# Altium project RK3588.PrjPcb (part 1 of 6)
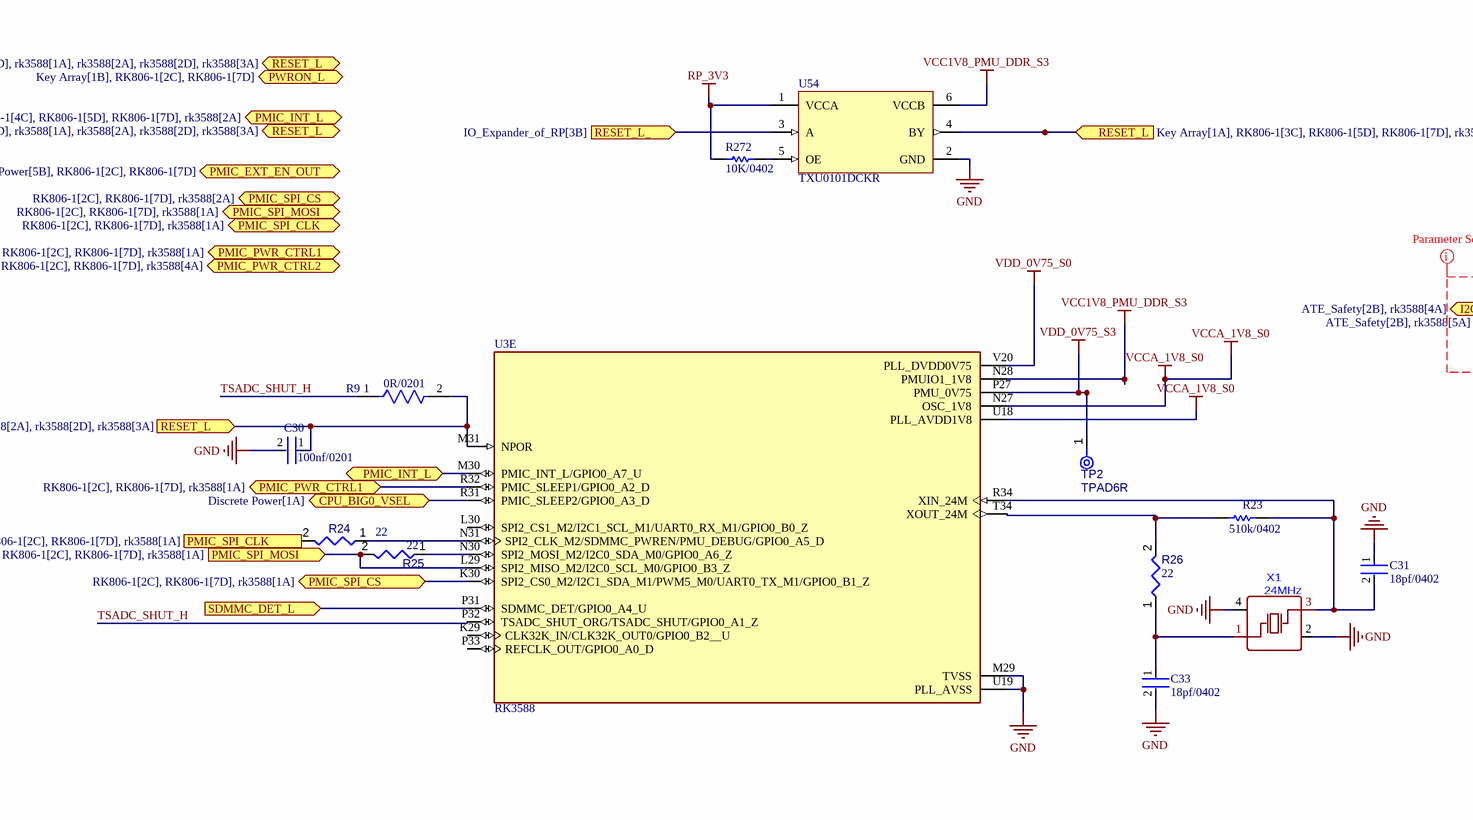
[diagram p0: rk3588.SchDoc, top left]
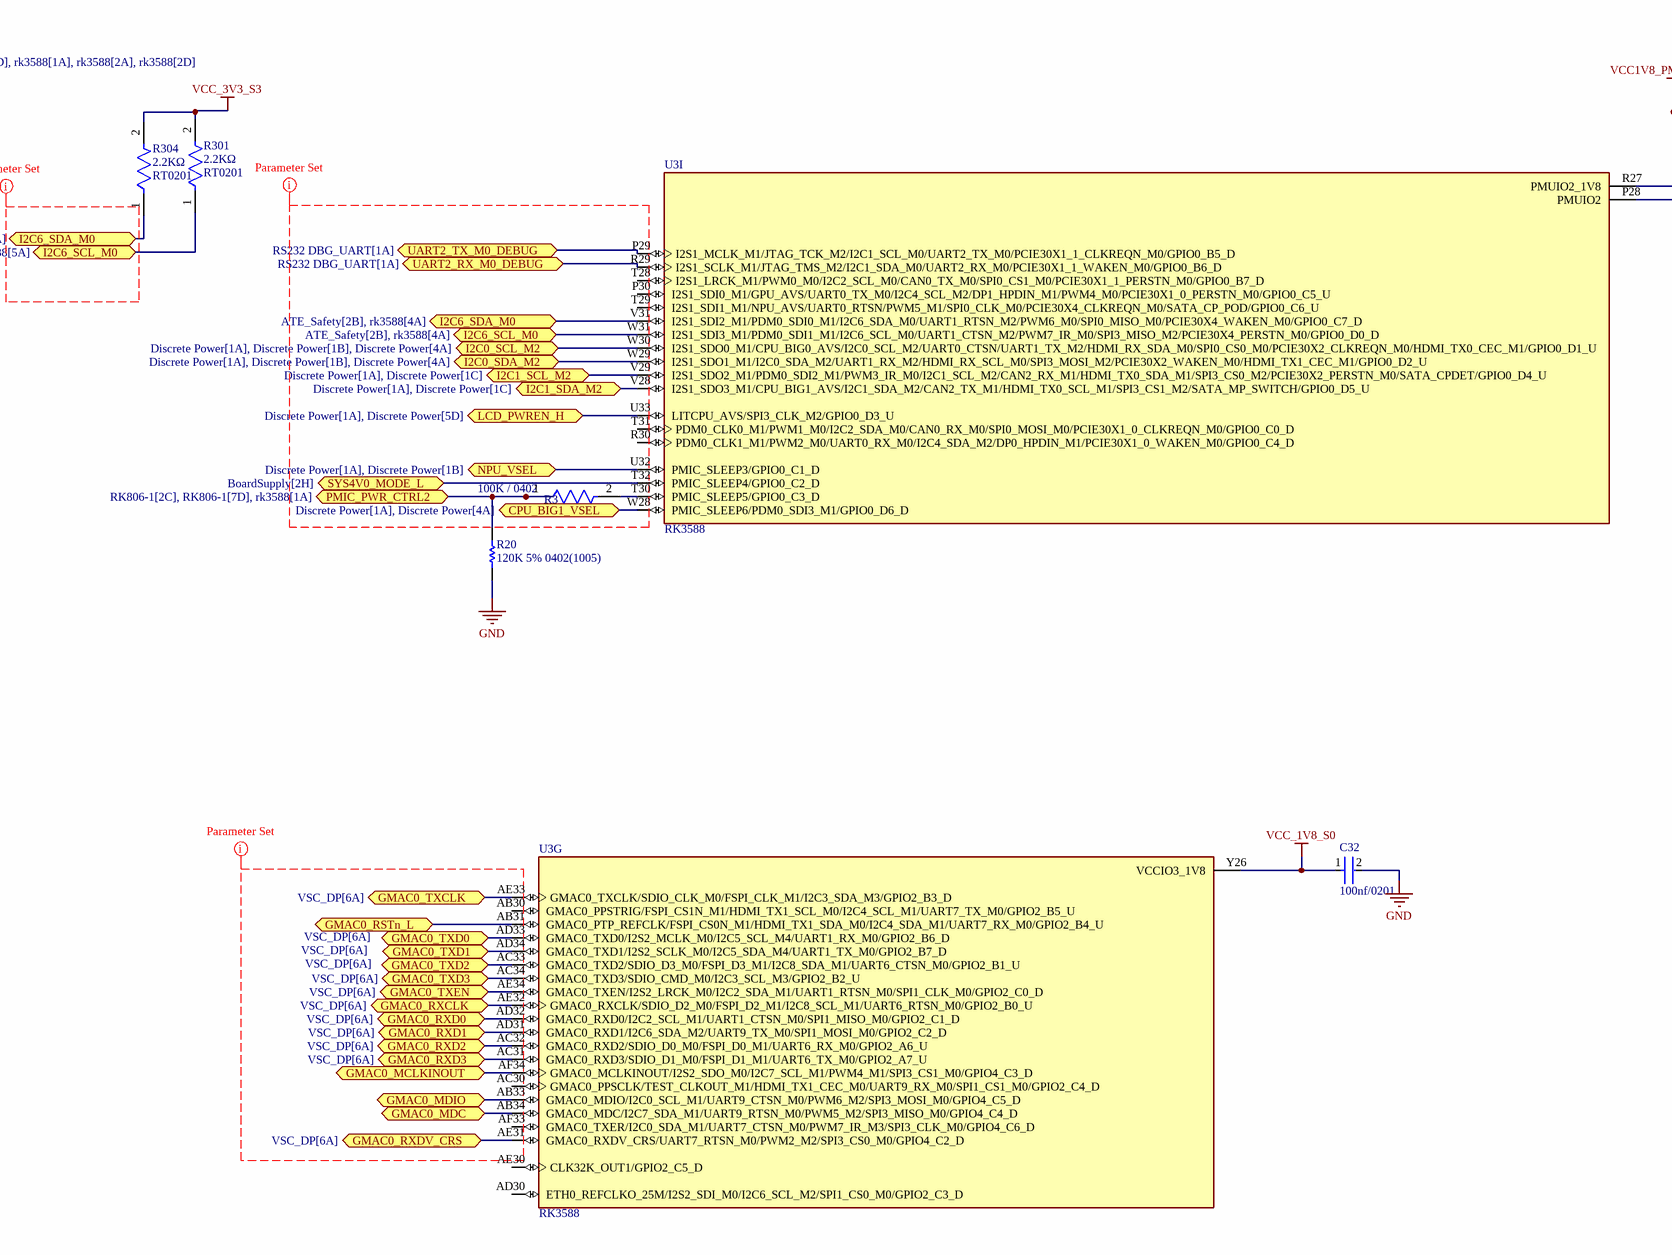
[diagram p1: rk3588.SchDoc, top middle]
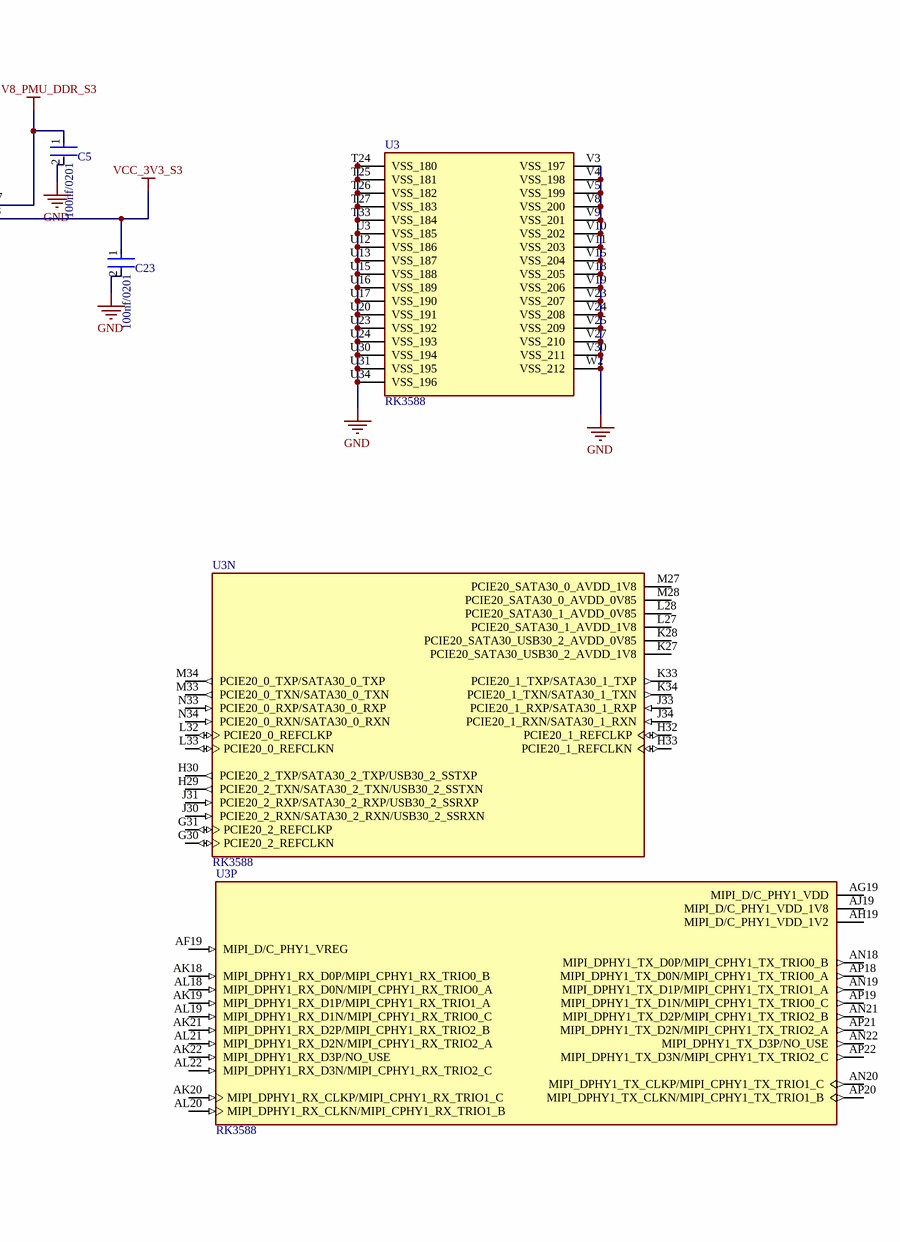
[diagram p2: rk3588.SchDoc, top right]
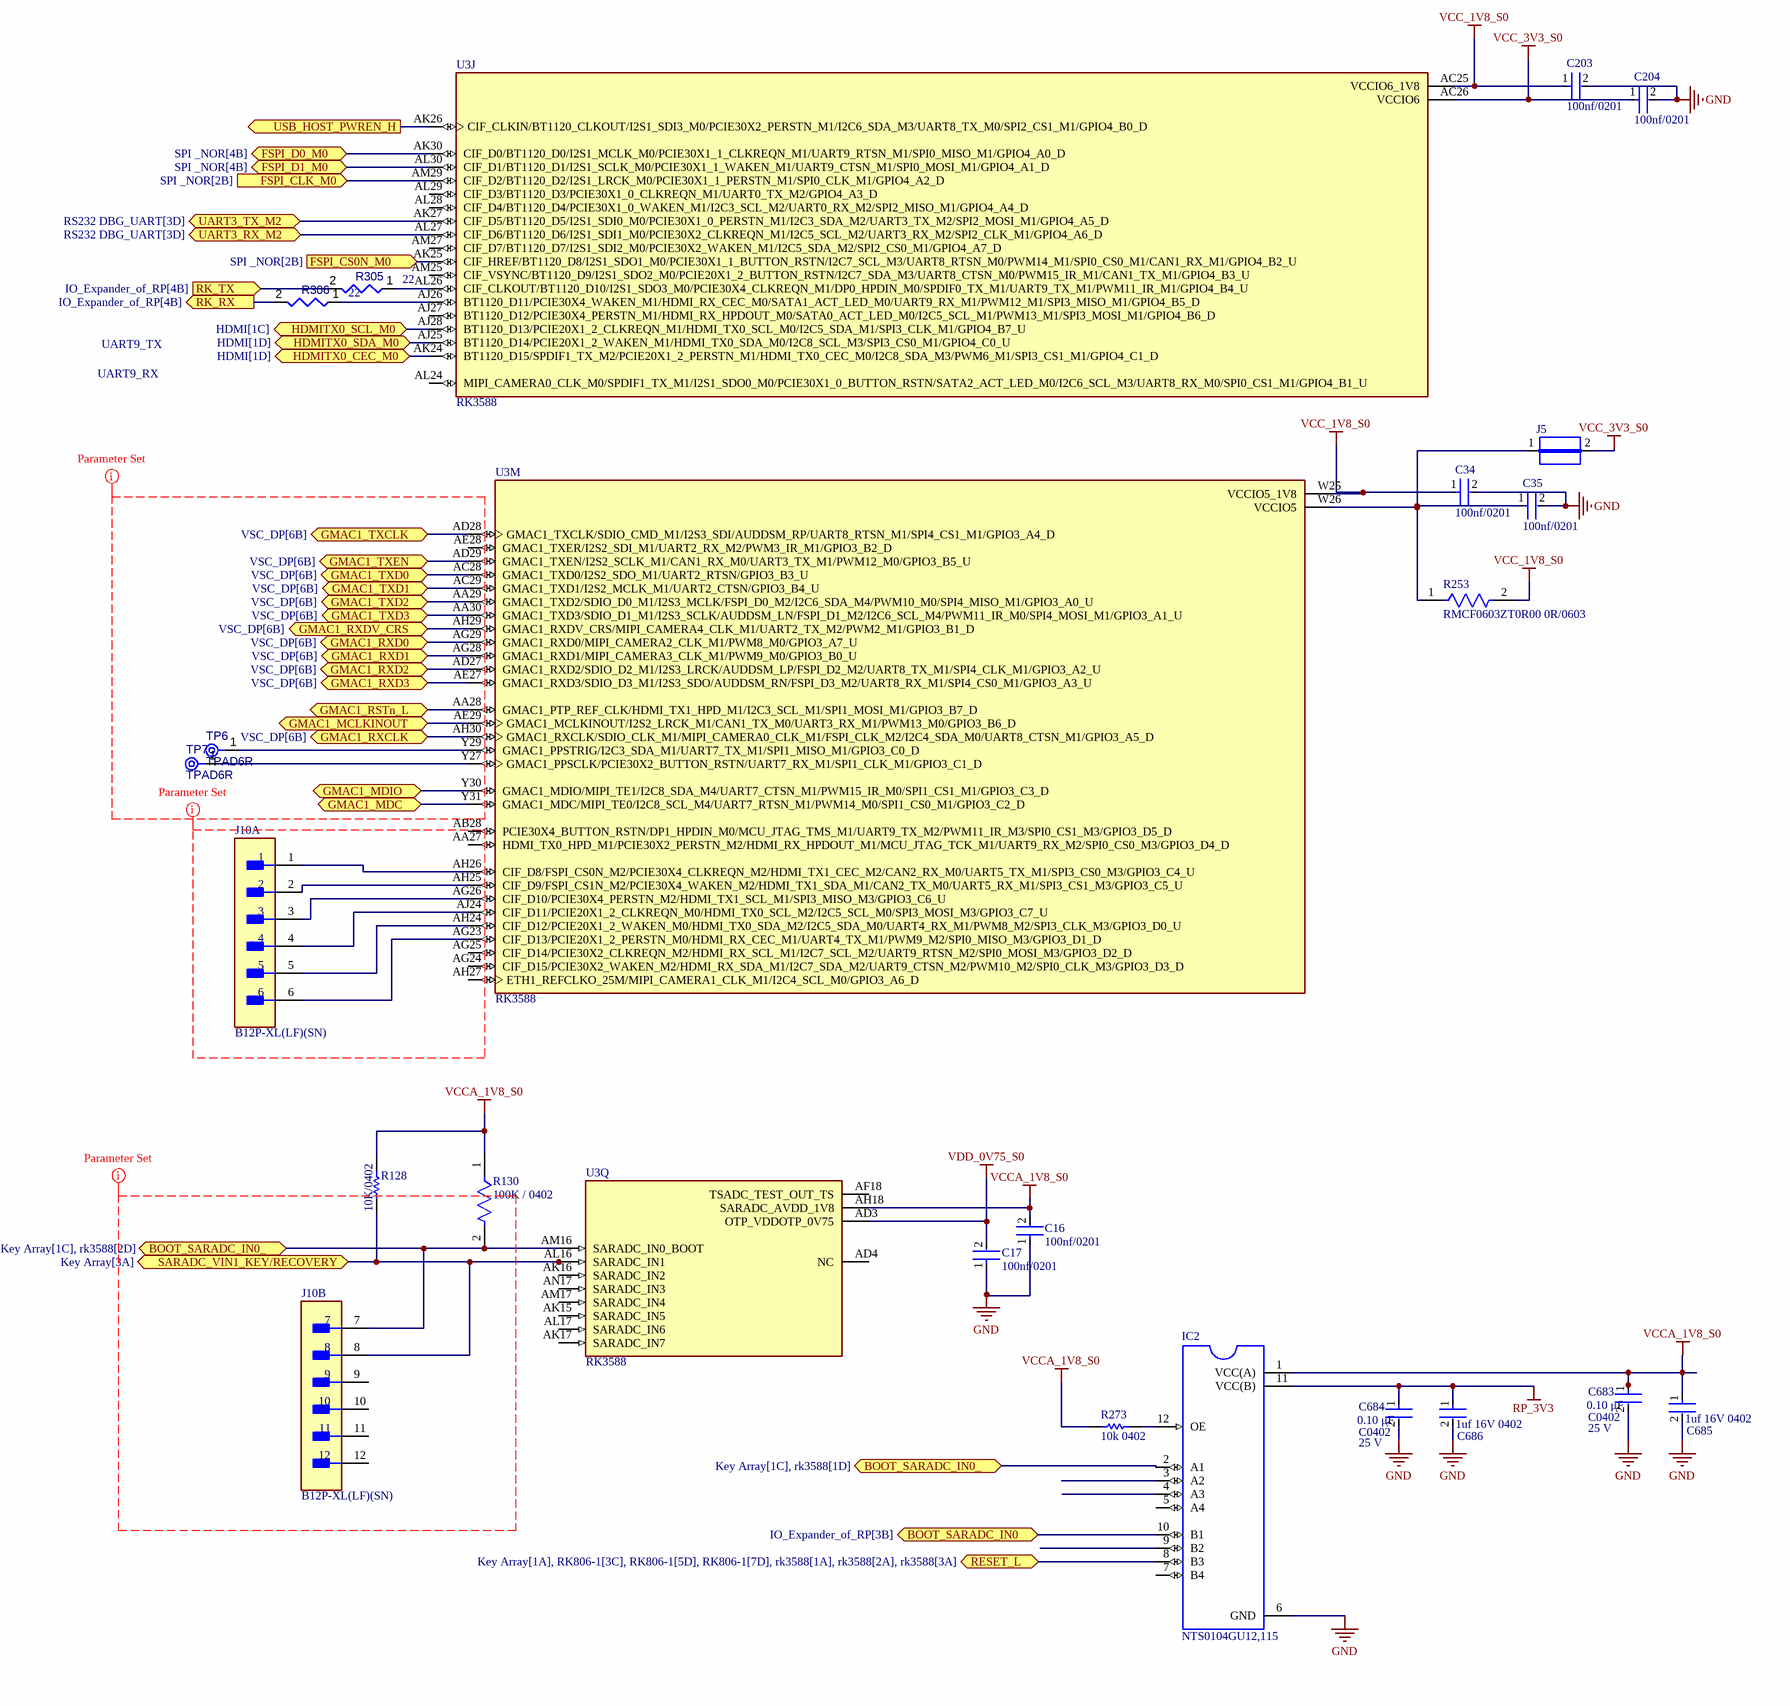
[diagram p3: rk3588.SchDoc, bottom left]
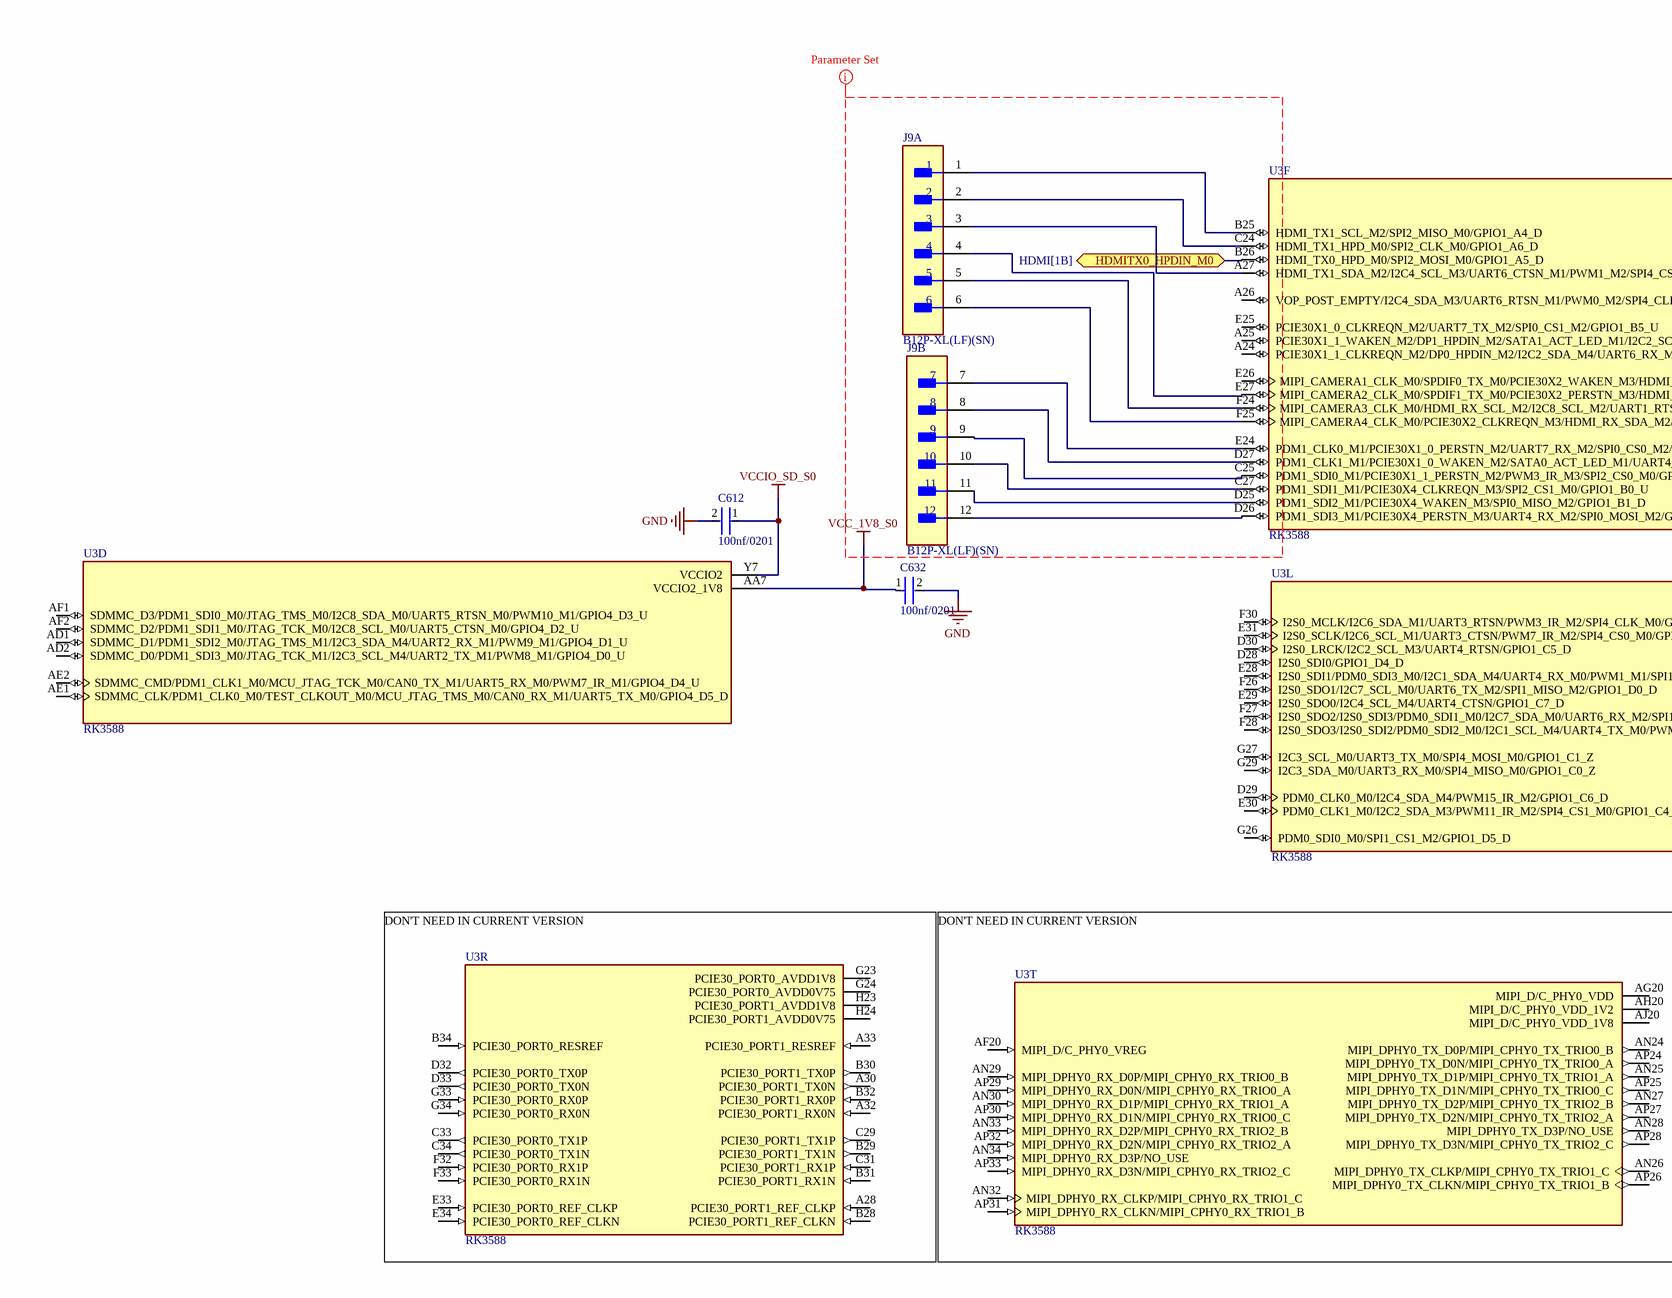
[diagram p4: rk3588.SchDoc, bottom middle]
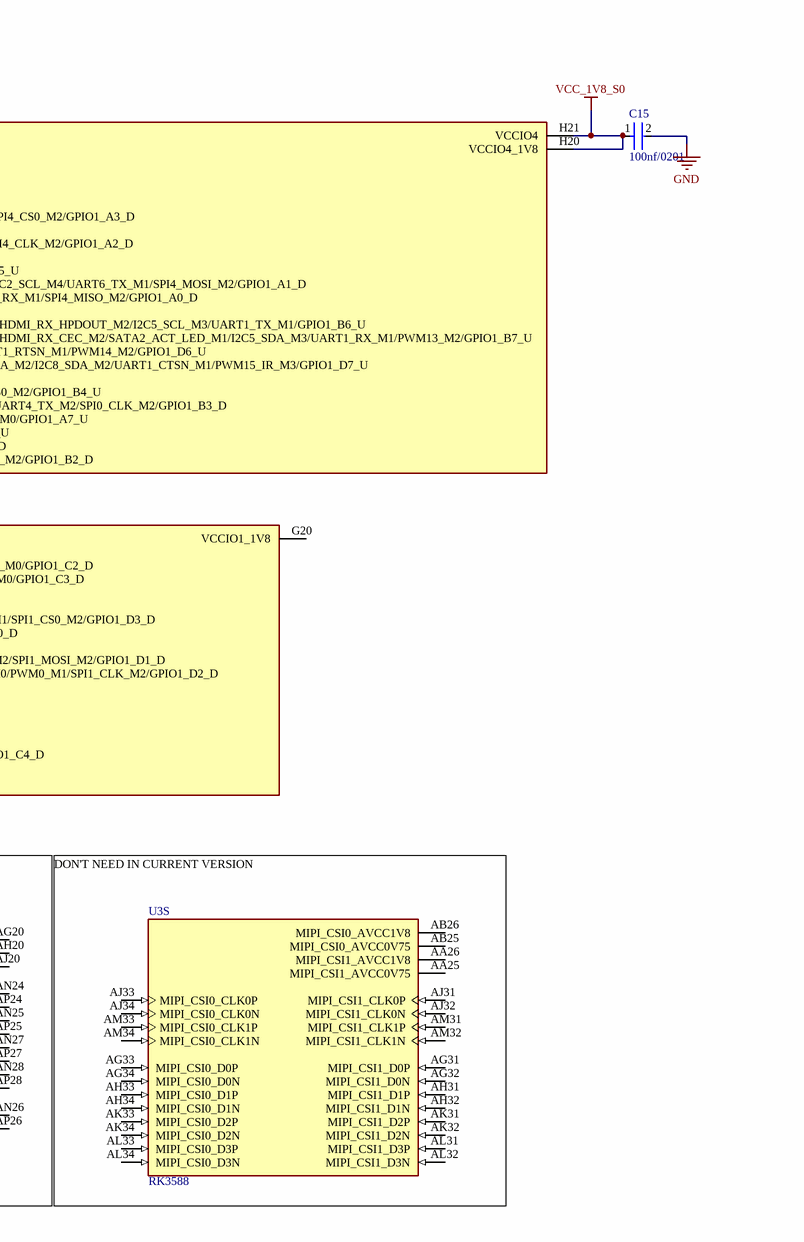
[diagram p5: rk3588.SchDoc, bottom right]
22 sheets, 1254 parts. Net scope: flat (ports and power ports of the same name join across sheets).
Board files: PCB1.PcbDoc, rk860_fp.pcbdoc
Sheets:
  rk3588.SchDoc
  RK3588_Power.SchDoc
  rk3588_LPDDR4.SchDoc
  RK806-1.SchDoc
  ATE_Safety.SchDoc
  SPI _NOR.SchDoc
  LAN9696.SchDoc
  LAN9696_Supply.SchDoc
  LAN_Supply.SchDoc
  8841.SchDoc
  EMMC.SchDoc
  LPDDR4_EDA.SchDoc
  BoardSupply.SchDoc
  RK3588_USB2.0_USB3.0.SchDoc
  HDMI.SchDoc
  Discrete Power.SchDoc
  RS232 DBG_UART.SchDoc
  Key Array.SchDoc
  RP2350.SchDoc
  IO_Expander_of_RP.SchDoc
  VSC_DP.SchDoc
  Level_Shifter.SchDoc

## Sheet rk3588.SchDoc
size D; SheetNumber: 1; SheetTotal: 22

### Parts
C5  100nf/0201  [FP-CL03-IPC_C]
C15  100nf/0201  [FP-CL03-IPC_C]
C16  100nf/0201  [FP-CL03-IPC_C]
C17  100nf/0201  [FP-CL03-IPC_C]
C23  100nf/0201  [FP-CL03-IPC_C]
C30  100nf/0201  [FP-CL03-IPC_C]
C31  18pf/0402  [FP-C0402-BB-MFG]
C32  100nf/0201  [FP-CL03-IPC_C]
C33  18pf/0402  [FP-C0402-BB-MFG]
C34  100nf/0201  [FP-CL03-IPC_C]
C35  100nf/0201  [FP-CL03-IPC_C]
C203  100nf/0201  [FP-CL03-IPC_C]
C204  100nf/0201  [FP-CL03-IPC_C]
C612  100nf/0201  [FP-CL03-IPC_C]
C632  100nf/0201  [FP-CL03-IPC_C]
C683  value 0.10 μF  Package: C0402  Voltage Rating: 25 V  [FP-C0402-BB-MFG]  (hidden comment: C0402C104M3PAC7867)
C684  value 0.10 μF  Package: C0402  Voltage Rating: 25 V  [FP-C0402-BB-MFG]  (hidden comment: C0402C104M3PAC7867)
C685  1uf 16V 0402  [FP-CC0402-MFG]
C686  1uf 16V 0402  [FP-CC0402-MFG]
IC2  NTS0104GU12,115  [QFN40P170X200X50-12N]
J5  JUMPER  [JUMPER]  (value not drawn)
J9  B12P-XL(LF)(SN)  [FP-B12P-XL_LF_SN-MFG]  (parts A,B of 2)
J10  B12P-XL(LF)(SN)  [FP-B12P-XL_LF_SN-MFG]  (parts A,B of 2)
R3  100K / 0402  [FP-CRGP0402-IPC_C]
R9  0R/0201  [FP-RMCF0201-IPC_C]
R20  120K 5% 0402(1005)  [RESC0402(1005)_M]
R23  510k/0402  [RESC1005X40X25NL05T10]
R24  value 22  [RESC0402(1005)_L]  (hidden comment: 22R2J)
R25  value 22  [RESC0402(1005)_L]  (hidden comment: 22R2J)
R26  value 22  [RESC0402(1005)_L]  (hidden comment: 22R2J)
R128  10K/0402  [RESC1005X40X20NL05T10]
R130  100K / 0402  [FP-CRGP0402-IPC_C]
R253  RMCF0603ZT0R00 0R/0603  [FP-RMCF0603-MFG]
R272  10K/0402  [RESC1005X40X20NL05T10]
R273  10k 0402  [RESC1005X40X20NL05T10]
R301  Resistance: 2.2KΩ  Package: RT0201  [FP-RT0201-MFG]  (hidden comment: RT0201FRE072K2L)
R304  Resistance: 2.2KΩ  Package: RT0201  [FP-RT0201-MFG]  (hidden comment: RT0201FRE072K2L)
R305  value 22  [RESC0402(1005)_L]  (hidden comment: 22R2J)
R306  value 22  [RESC0402(1005)_L]  (hidden comment: 22R2J)
TP2  TPAD6R  [TP06R]  (no BOM)
TP6  TPAD6R  [TP06R]  (no BOM)
TP7  TPAD6R  [TP06R]  (no BOM)
U3  RK3588  [BGA1088C65P34X34_2300X2300X204N]  (parts D,E,F,G,I,J,L,M,N,P,Q,R,S,T,27 of 30)
U54  TXU0101DCKR  [FP-DCK0006A-MFG]
X1  24MHz  [CRYSTAL-SMD_4P-L3.2-W2.5-BL]

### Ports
BOOT_SARADC_IN0 (bidir, see IO_Expander_of_RP[3B]), BOOT_SARADC_IN0_ (bidir, see Key Array[1C], rk3588[1D]), BOOT_SARADC_IN0_ (bidir, see Key Array[1C], rk3588[2D]), CPU_BIG0_VSEL (bidir, see Discrete Power[1A]), CPU_BIG1_VSEL (bidir, see Discrete Power[1A], Discrete Power[4A]), FSPI_CLK_M0 (in, see SPI _NOR[2B]), FSPI_CS0N_M0 (in, see SPI _NOR[2B]), FSPI_D0_M0 (bidir, see SPI _NOR[4B]), FSPI_D1_M0 (bidir, see SPI _NOR[4B]), GMAC0_MCLKINOUT (bidir), GMAC0_MDC (bidir), GMAC0_MDIO (bidir), GMAC0_RSTn_L (bidir), GMAC0_RXCLK (bidir, see VSC_DP[6A]), GMAC0_RXD0 (bidir, see VSC_DP[6A]), GMAC0_RXD1 (bidir, see VSC_DP[6A]), GMAC0_RXD2 (bidir, see VSC_DP[6A]), GMAC0_RXD3 (bidir, see VSC_DP[6A]), GMAC0_RXDV_CRS (bidir, see VSC_DP[6A]), GMAC0_TXCLK (bidir, see VSC_DP[6A]), GMAC0_TXD0 (bidir, see VSC_DP[6A]), GMAC0_TXD1 (bidir, see VSC_DP[6A]), GMAC0_TXD2 (bidir, see VSC_DP[6A]), GMAC0_TXD3 (bidir, see VSC_DP[6A]), GMAC0_TXEN (bidir, see VSC_DP[6A]), GMAC1_MCLKINOUT (bidir), GMAC1_MDC (bidir), GMAC1_MDIO (bidir), GMAC1_RSTn_L (bidir), GMAC1_RXCLK (bidir, see VSC_DP[6B]), GMAC1_RXD0 (bidir, see VSC_DP[6B]), GMAC1_RXD1 (bidir, see VSC_DP[6B]), GMAC1_RXD2 (bidir, see VSC_DP[6B]), GMAC1_RXD3 (bidir, see VSC_DP[6B]), GMAC1_RXDV_CRS (bidir, see VSC_DP[6B]), GMAC1_TXCLK (bidir, see VSC_DP[6B]), GMAC1_TXD0 (bidir, see VSC_DP[6B]), GMAC1_TXD1 (bidir, see VSC_DP[6B]), GMAC1_TXD2 (bidir, see VSC_DP[6B]), GMAC1_TXD3 (bidir, see VSC_DP[6B]), GMAC1_TXEN (bidir, see VSC_DP[6B]), HDMITX0_CEC_M0 (bidir, see HDMI[1D]), HDMITX0_HPDIN_M0 (bidir, see HDMI[1B]), HDMITX0_SCL_M0 (bidir, see HDMI[1C]), HDMITX0_SDA_M0 (bidir, see HDMI[1D]), I2C0_SCL_M2 (bidir, see Discrete Power[1A], Discrete Power[1B], Discrete Power[4A]), I2C0_SDA_M2 (bidir, see Discrete Power[1A], Discrete Power[1B], Discrete Power[4A]), I2C1_SCL_M2 (bidir, see Discrete Power[1A], Discrete Power[1C]), I2C1_SDA_M2 (bidir, see Discrete Power[1A], Discrete Power[1C]), I2C6_SCL_M0 (bidir, see ATE_Safety[2B], rk3588[4A]), I2C6_SCL_M0 (bidir, see ATE_Safety[2B], rk3588[5A]), I2C6_SDA_M0 (bidir, see ATE_Safety[2B], rk3588[4A]), LCD_PWREN_H (bidir, see Discrete Power[1A], Discrete Power[5D]), NPU_VSEL (bidir, see Discrete Power[1A], Discrete Power[1B]), PMIC_EXT_EN_OUT (bidir, see Discrete Power[5B], RK806-1[2C], RK806-1[7D]), PMIC_INT_L (bidir, see RK806-1[4C], RK806-1[5D], RK806-1[7D], rk3588[1A]), PMIC_INT_L (bidir, see RK806-1[4C], RK806-1[5D], RK806-1[7D], rk3588[2A]), PMIC_PWR_CTRL1 (bidir, see RK806-1[2C], RK806-1[7D], rk3588[1A]), PMIC_PWR_CTRL2 (bidir, see RK806-1[2C], RK806-1[7D], rk3588[1A]), PMIC_PWR_CTRL2 (bidir, see RK806-1[2C], RK806-1[7D], rk3588[4A]), PMIC_SPI_CLK (bidir, see RK806-1[2C], RK806-1[7D], rk3588[1A]), PMIC_SPI_CLK (in, see RK806-1[2C], RK806-1[7D], rk3588[1A]), PMIC_SPI_CS (bidir, see RK806-1[2C], RK806-1[7D], rk3588[1A]), PMIC_SPI_CS (bidir, see RK806-1[2C], RK806-1[7D], rk3588[2A]), PMIC_SPI_MOSI (bidir, see RK806-1[2C], RK806-1[7D], rk3588[1A]), PMIC_SPI_MOSI (in, see RK806-1[2C], RK806-1[7D], rk3588[1A]), PWRON_L (bidir, see Key Array[1B], RK806-1[2C], RK806-1[7D]), RESET_L (bidir, see Key Array[1A], RK806-1[3C], RK806-1[5D], RK806-1[7D], rk3588[1A], rk3588[2A], rk3588[2D], rk3588[3A]), RESET_L (bidir, see Key Array[1A], RK806-1[3C], RK806-1[5D], RK806-1[7D], rk3588[1A], rk3588[2A], rk3588[3A]), RESET_L (in, see Key Array[1A], RK806-1[3C], RK806-1[5D], RK806-1[7D], rk3588[1A], rk3588[2A], rk3588[2D]), RESET_L (in, see Key Array[1A], RK806-1[3C], RK806-1[5D], RK806-1[7D], rk3588[2A], rk3588[2D], rk3588[3A]), RESET_L_ (in, see IO_Expander_of_RP[3B]), RK_RX (out, see IO_Expander_of_RP[4B]), RK_TX (in, see IO_Expander_of_RP[4B]), SARADC_VIN1_KEY/RECOVERY (bidir, see Key Array[3A]), SDMMC_DET_L (in), SYS4V0_MODE_L (bidir, see BoardSupply[2H]), UART2_RX_M0_DEBUG (bidir, see RS232 DBG_UART[1A]), UART2_TX_M0_DEBUG (bidir, see RS232 DBG_UART[1A]), UART3_RX_M2 (bidir, see RS232 DBG_UART[3D]), UART3_TX_M2 (bidir, see RS232 DBG_UART[3D]), USB_HOST_PWREN_H (out)

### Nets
GND: C5.2 C15.2 C16.1 C17.1 C23.2 C30.2 C31.1 C32.2 C33.2 C34.2 C35.2 C203.2 C204.2 C612.2 C632.2 C683.2 C684.2 C685.2 C686.2 IC2.6(GND) R20.1 U3.M29(TVSS) U3.T24(VSS_180) U3.T25(VSS_181) U3.T26(VSS_182) U3.T27(VSS_183) U3.T33(VSS_184) U3.U3(VSS_185) U3.U12(VSS_186) U3.U13(VSS_187) U3.U15(VSS_188) U3.U16(VSS_189) U3.U17(VSS_190) U3.U19(PLL_AVSS) U3.U20(VSS_191) U3.U23(VSS_192) U3.U24(VSS_193) U3.U30(VSS_194) U3.U31(VSS_195) U3.U34(VSS_196) U3.V3(VSS_197) U3.V4(VSS_198) U3.V5(VSS_199) U3.V8(VSS_200) U3.V9(VSS_201) U3.V10(VSS_202) U3.V11(VSS_203) U3.V15(VSS_204) U3.V18(VSS_205) U3.V19(VSS_206) U3.V23(VSS_207) U3.V24(VSS_208) U3.V25(VSS_209) U3.V27(VSS_210) U3.V30(VSS_211) U3.W2(VSS_212) U54.2(GND) X1.2(GND) X1.4(GND)
RP_3V3: C684.1 C686.1 IC2.11(VCC(B)) R272.2 U54.1(VCCA)  [project net 3V3]
VCC1V8_PMU_DDR_S3: C5.1 U3.N28(PMUIO1_1V8) U3.R27(PMUIO2_1V8) U54.6(VCCB)
VCC_1V8_S0: C15.1 C32.1 C34.1 C203.1 C632.1 R253.2 U3.AA7(VCCIO2_1V8) U3.AC25(VCCIO6_1V8) U3.H20(VCCIO4_1V8) U3.H21(VCCIO4) U3.W25(VCCIO5_1V8) U3.Y26(VCCIO3_1V8)
VCC_3V3_S0: C204.1 J5.2 U3.AC26(VCCIO6)
VCC_3V3_S3: C23.1 R301.2 R304.2 U3.P28(PMUIO2)  [project net EMMC_VCC]
VCCA_1V8_S0: C16.2 C683.1 C685.1 IC2.1(VCC(A)) R128.2 R130.1 R273.1 U3.AH18(SARADC_AVDD_1V8) U3.N27(OSC_1V8) U3.U18(PLL_AVDD1V8)  [project net VCCA_1V8]
VCCIO_SD_S0: C612.1 U3.Y7(VCCIO2)  [project net PLDO5]
VDD_0V75_S0: C17.2 U3.AD3(OTP_VDDOTP_0V75) U3.V20(PLL_DVDD0V75)  [project net NLDO5]
VDD_0V75_S3: TP2.1(TP) U3.P27(PMU_0V75)  [project net NLDO1]
BOOT_SARADC_IN0: IC2.10(B1) ; port BOOT_SARADC_IN0
BOOT_SARADC_IN0_: IC2.2(A1) J10.7 R130.2 U3.AM16(SARADC_IN0_BOOT) ; port BOOT_SARADC_IN0_
CPU_BIG0_VSEL: U3.R31(PMIC_SLEEP2/GPIO0_A3_D) ; port CPU_BIG0_VSEL
CPU_BIG1_VSEL: U3.W28(PMIC_SLEEP6/PDM0_SDI3_M1/GPIO0_D6_D) ; port CPU_BIG1_VSEL
FSPI_CLK_M0: U3.AM29(CIF_D2/BT1120_D2/I2S1_LRCK_M0/PCIE30X1_1_PERSTN_M1/SPI0_CLK_M1/GPIO4_A2_D) ; port FSPI_CLK_M0
FSPI_CS0N_M0: U3.AK25(CIF_HREF/BT1120_D8/I2S1_SDO1_M0/PCIE30X1_1_BUTTON_RSTN/I2C7_SCL_M3/UART8_RTSN_M0/PWM14_M1/SPI0_CS0_M1/CAN1_RX_M1/GPIO4_B2_U) ; port FSPI_CS0N_M0
FSPI_D0_M0: U3.AK30(CIF_D0/BT1120_D0/I2S1_MCLK_M0/PCIE30X1_1_CLKREQN_M1/UART9_RTSN_M1/SPI0_MISO_M1/GPIO4_A0_D) ; port FSPI_D0_M0
FSPI_D1_M0: U3.AL30(CIF_D1/BT1120_D1/I2S1_SCLK_M0/PCIE30X1_1_WAKEN_M1/UART9_CTSN_M1/SPI0_MOSI_M1/GPIO4_A1_D) ; port FSPI_D1_M0
GMAC0_MCLKINOUT: U3.AF34(GMAC0_MCLKINOUT/I2S2_SDO_M0/I2C7_SCL_M1/PWM4_M1/SPI3_CS1_M0/GPIO4_C3_D) ; port GMAC0_MCLKINOUT
GMAC0_MDC: U3.AB34(GMAC0_MDC/I2C7_SDA_M1/UART9_RTSN_M0/PWM5_M2/SPI3_MISO_M0/GPIO4_C4_D) ; port GMAC0_MDC
GMAC0_MDIO: U3.AB33(GMAC0_MDIO/I2C0_SCL_M1/UART9_CTSN_M0/PWM6_M2/SPI3_MOSI_M0/GPIO4_C5_D) ; port GMAC0_MDIO
GMAC0_RSTn_L: U3.AB31(GMAC0_PTP_REFCLK/FSPI_CS0N_M1/HDMI_TX1_SDA_M0/I2C4_SDA_M1/UART7_RX_M0/GPIO2_B4_U) ; port GMAC0_RSTn_L
GMAC0_RXCLK: U3.AE32(GMAC0_RXCLK/SDIO_D2_M0/FSPI_D2_M1/I2C8_SCL_M1/UART6_RTSN_M0/GPIO2_B0_U) ; port GMAC0_RXCLK
GMAC0_RXD0: U3.AD32(GMAC0_RXD0/I2C2_SCL_M1/UART1_CTSN_M0/SPI1_MISO_M0/GPIO2_C1_D) ; port GMAC0_RXD0
GMAC0_RXD1: U3.AD31(GMAC0_RXD1/I2C6_SDA_M2/UART9_TX_M0/SPI1_MOSI_M0/GPIO2_C2_D) ; port GMAC0_RXD1
GMAC0_RXD2: U3.AC32(GMAC0_RXD2/SDIO_D0_M0/FSPI_D0_M1/UART6_RX_M0/GPIO2_A6_U) ; port GMAC0_RXD2
GMAC0_RXD3: U3.AC31(GMAC0_RXD3/SDIO_D1_M0/FSPI_D1_M1/UART6_TX_M0/GPIO2_A7_U) ; port GMAC0_RXD3
GMAC0_RXDV_CRS: U3.AE31(GMAC0_RXDV_CRS/UART7_RTSN_M0/PWM2_M2/SPI3_CS0_M0/GPIO4_C2_D) ; port GMAC0_RXDV_CRS
GMAC0_TXCLK: U3.AE33(GMAC0_TXCLK/SDIO_CLK_M0/FSPI_CLK_M1/I2C3_SDA_M3/GPIO2_B3_D) ; port GMAC0_TXCLK
GMAC0_TXD0: U3.AD33(GMAC0_TXD0/I2S2_MCLK_M0/I2C5_SCL_M4/UART1_RX_M0/GPIO2_B6_D) ; port GMAC0_TXD0
GMAC0_TXD1: U3.AD34(GMAC0_TXD1/I2S2_SCLK_M0/I2C5_SDA_M4/UART1_TX_M0/GPIO2_B7_D) ; port GMAC0_TXD1
GMAC0_TXD2: U3.AC33(GMAC0_TXD2/SDIO_D3_M0/FSPI_D3_M1/I2C8_SDA_M1/UART6_CTSN_M0/GPIO2_B1_U) ; port GMAC0_TXD2
GMAC0_TXD3: U3.AC34(GMAC0_TXD3/SDIO_CMD_M0/I2C3_SCL_M3/GPIO2_B2_U) ; port GMAC0_TXD3
GMAC0_TXEN: U3.AE34(GMAC0_TXEN/I2S2_LRCK_M0/I2C2_SDA_M1/UART1_RTSN_M0/SPI1_CLK_M0/GPIO2_C0_D) ; port GMAC0_TXEN
GMAC1_MCLKINOUT: U3.AE29(GMAC1_MCLKINOUT/I2S2_LRCK_M1/CAN1_TX_M0/UART3_RX_M1/PWM13_M0/GPIO3_B6_D) ; port GMAC1_MCLKINOUT
GMAC1_MDC: U3.Y31(GMAC1_MDC/MIPI_TE0/I2C8_SCL_M4/UART7_RTSN_M1/PWM14_M0/SPI1_CS0_M1/GPIO3_C2_D) ; port GMAC1_MDC
GMAC1_MDIO: U3.Y30(GMAC1_MDIO/MIPI_TE1/I2C8_SDA_M4/UART7_CTSN_M1/PWM15_IR_M0/SPI1_CS1_M1/GPIO3_C3_D) ; port GMAC1_MDIO
GMAC1_RSTn_L: U3.AA28(GMAC1_PTP_REF_CLK/HDMI_TX1_HPD_M1/I2C3_SCL_M1/SPI1_MOSI_M1/GPIO3_B7_D) ; port GMAC1_RSTn_L
GMAC1_RXCLK: U3.AH30(GMAC1_RXCLK/SDIO_CLK_M1/MIPI_CAMERA0_CLK_M1/FSPI_CLK_M2/I2C4_SDA_M0/UART8_CTSN_M1/GPIO3_A5_D) ; port GMAC1_RXCLK
GMAC1_RXD0: U3.AG29(GMAC1_RXD0/MIPI_CAMERA2_CLK_M1/PWM8_M0/GPIO3_A7_U) ; port GMAC1_RXD0
GMAC1_RXD1: U3.AG28(GMAC1_RXD1/MIPI_CAMERA3_CLK_M1/PWM9_M0/GPIO3_B0_U) ; port GMAC1_RXD1
GMAC1_RXD2: U3.AD27(GMAC1_RXD2/SDIO_D2_M1/I2S3_LRCK/AUDDSM_LP/FSPI_D2_M2/UART8_TX_M1/SPI4_CLK_M1/GPIO3_A2_U) ; port GMAC1_RXD2
GMAC1_RXD3: U3.AE27(GMAC1_RXD3/SDIO_D3_M1/I2S3_SDO/AUDDSM_RN/FSPI_D3_M2/UART8_RX_M1/SPI4_CS0_M1/GPIO3_A3_U) ; port GMAC1_RXD3
GMAC1_RXDV_CRS: U3.AH29(GMAC1_RXDV_CRS/MIPI_CAMERA4_CLK_M1/UART2_TX_M2/PWM2_M1/GPIO3_B1_D) ; port GMAC1_RXDV_CRS
GMAC1_TXCLK: U3.AD28(GMAC1_TXCLK/SDIO_CMD_M1/I2S3_SDI/AUDDSM_RP/UART8_RTSN_M1/SPI4_CS1_M1/GPIO3_A4_D) ; port GMAC1_TXCLK
GMAC1_TXD0: U3.AC28(GMAC1_TXD0/I2S2_SDO_M1/UART2_RTSN/GPIO3_B3_U) ; port GMAC1_TXD0
GMAC1_TXD1: U3.AC29(GMAC1_TXD1/I2S2_MCLK_M1/UART2_CTSN/GPIO3_B4_U) ; port GMAC1_TXD1
GMAC1_TXD2: U3.AA29(GMAC1_TXD2/SDIO_D0_M1/I2S3_MCLK/FSPI_D0_M2/I2C6_SDA_M4/PWM10_M0/SPI4_MISO_M1/GPIO3_A0_U) ; port GMAC1_TXD2
GMAC1_TXD3: U3.AA30(GMAC1_TXD3/SDIO_D1_M1/I2S3_SCLK/AUDDSM_LN/FSPI_D1_M2/I2C6_SCL_M4/PWM11_IR_M0/SPI4_MOSI_M1/GPIO3_A1_U) ; port GMAC1_TXD3
GMAC1_TXEN: U3.AD29(GMAC1_TXEN/I2S2_SCLK_M1/CAN1_RX_M0/UART3_TX_M1/PWM12_M0/GPIO3_B5_U) ; port GMAC1_TXEN
HDMITX0_CEC_M0: U3.AK24(BT1120_D15/SPDIF1_TX_M2/PCIE20X1_2_PERSTN_M1/HDMI_TX0_CEC_M0/I2C8_SDA_M3/PWM6_M1/SPI3_CS1_M1/GPIO4_C1_D) ; port HDMITX0_CEC_M0
HDMITX0_HPDIN_M0: U3.B26(HDMI_TX0_HPD_M0/SPI2_MOSI_M0/GPIO1_A5_D) ; port HDMITX0_HPDIN_M0
HDMITX0_SCL_M0: U3.AJ28(BT1120_D13/PCIE20X1_2_CLKREQN_M1/HDMI_TX0_SCL_M0/I2C5_SDA_M1/SPI3_CLK_M1/GPIO4_B7_U) ; port HDMITX0_SCL_M0
HDMITX0_SDA_M0: U3.AJ25(BT1120_D14/PCIE20X1_2_WAKEN_M1/HDMI_TX0_SDA_M0/I2C8_SCL_M3/SPI3_CS0_M1/GPIO4_C0_U) ; port HDMITX0_SDA_M0
I2C0_SCL_M2: U3.W30(I2S1_SDO0_M1/CPU_BIG0_AVS/I2C0_SCL_M2/UART0_CTSN/UART1_TX_M2/HDMI_RX_SDA_M0/SPI0_CS0_M0/PCIE30X2_CLKREQN_M0/HDMI_TX0_CEC_M1/GPIO0_D1_U) ; port I2C0_SCL_M2
I2C0_SDA_M2: U3.W29(I2S1_SDO1_M1/I2C0_SDA_M2/UART1_RX_M2/HDMI_RX_SCL_M0/SPI3_MOSI_M2/PCIE30X2_WAKEN_M0/HDMI_TX1_CEC_M1/GPIO0_D2_U) ; port I2C0_SDA_M2
I2C1_SCL_M2: U3.V29(I2S1_SDO2_M1/PDM0_SDI2_M1/PWM3_IR_M0/I2C1_SCL_M2/CAN2_RX_M1/HDMI_TX0_SDA_M1/SPI3_CS0_M2/PCIE30X2_PERSTN_M0/SATA_CPDET/GPIO0_D4_U) ; port I2C1_SCL_M2
I2C1_SDA_M2: U3.V28(I2S1_SDO3_M1/CPU_BIG1_AVS/I2C1_SDA_M2/CAN2_TX_M1/HDMI_TX0_SCL_M1/SPI3_CS1_M2/SATA_MP_SWITCH/GPIO0_D5_U) ; port I2C1_SDA_M2
I2C6_SCL_M0: R301.1 U3.W31(I2S1_SDI3_M1/PDM0_SDI1_M1/I2C6_SCL_M0/UART1_CTSN_M2/PWM7_IR_M0/SPI3_MISO_M2/PCIE30X4_PERSTN_M0/GPIO0_D0_D) ; port I2C6_SCL_M0
I2C6_SDA_M0: R304.1 U3.V31(I2S1_SDI2_M1/PDM0_SDI0_M1/I2C6_SDA_M0/UART1_RTSN_M2/PWM6_M0/SPI0_MISO_M0/PCIE30X4_WAKEN_M0/GPIO0_C7_D) ; port I2C6_SDA_M0
LCD_PWREN_H: U3.U33(LITCPU_AVS/SPI3_CLK_M2/GPIO0_D3_U) ; port LCD_PWREN_H
NPU_VSEL: U3.U32(PMIC_SLEEP3/GPIO0_C1_D) ; port NPU_VSEL
PMIC_INT_L: U3.M30(PMIC_INT_L/GPIO0_A7_U) ; port PMIC_INT_L
PMIC_PWR_CTRL1: U3.R32(PMIC_SLEEP1/GPIO0_A2_D) ; port PMIC_PWR_CTRL1
PMIC_PWR_CTRL2: R3.1 R20.2 ; port PMIC_PWR_CTRL2
PMIC_SPI_CLK: R24.2 ; port PMIC_SPI_CLK
PMIC_SPI_CS: U3.K30(SPI2_CS0_M2/I2C1_SDA_M1/PWM5_M0/UART0_TX_M1/GPIO0_B1_Z) ; port PMIC_SPI_CS
PMIC_SPI_MOSI: R25.2 U3.L29(SPI2_MISO_M2/I2C0_SCL_M0/GPIO0_B3_Z) ; port PMIC_SPI_MOSI
RESET_L: C30.1 IC2.8(B3) R9.2 U3.M31(NPOR) U54.4(BY) ; port RESET_L
RESET_L_: U54.3(A) ; port RESET_L_
RK_RX: R306.2 ; port RK_RX
RK_TX: R305.2 ; port RK_TX
SARADC_VIN1_KEY/RECOVERY: J10.8 R128.1 U3.AL16(SARADC_IN1) ; port SARADC_VIN1_KEY/RECOVERY
SDMMC_DET_L: U3.P31(SDMMC_DET/GPIO0_A4_U) ; port SDMMC_DET_L
SYS4V0_MODE_L: U3.T32(PMIC_SLEEP4/GPIO0_C2_D) ; port SYS4V0_MODE_L
TSADC_SHUT_H: R9.1 U3.P32(TSADC_SHUT_ORG/TSADC_SHUT/GPIO0_A1_Z)
UART2_RX_M0_DEBUG: U3.R29(I2S1_SCLK_M1/JTAG_TMS_M2/I2C1_SDA_M0/UART2_RX_M0/PCIE30X1_1_WAKEN_M0/GPIO0_B6_D) ; port UART2_RX_M0_DEBUG
UART2_TX_M0_DEBUG: U3.P29(I2S1_MCLK_M1/JTAG_TCK_M2/I2C1_SCL_M0/UART2_TX_M0/PCIE30X1_1_CLKREQN_M0/GPIO0_B5_D) ; port UART2_TX_M0_DEBUG
UART3_RX_M2: U3.AL27(CIF_D6/BT1120_D6/I2S1_SDI1_M0/PCIE30X2_CLKREQN_M1/I2C5_SCL_M2/UART3_RX_M2/SPI2_CLK_M1/GPIO4_A6_D) ; port UART3_RX_M2
UART3_TX_M2: U3.AK27(CIF_D5/BT1120_D5/I2S1_SDI0_M0/PCIE30X1_0_PERSTN_M1/I2C3_SDA_M2/UART3_TX_M2/SPI2_MOSI_M1/GPIO4_A5_D) ; port UART3_TX_M2
USB_HOST_PWREN_H: U3.AK26(CIF_CLKIN/BT1120_CLKOUT/I2S1_SDI3_M0/PCIE30X2_PERSTN_M1/I2C6_SDA_M3/UART8_TX_M0/SPI2_CS1_M1/GPIO4_B0_D) ; port USB_HOST_PWREN_H
NetC31_2: C31.2 R23.1 U3.R34(XIN_24M) X1.3(OSC2)
NetC33_1: C33.1 R26.1 X1.1(OSC1)
NetC35_1: C35.1 J5.1 R253.1 U3.W26(VCCIO5)
NetIC2_12: IC2.12(OE) R273.2
NetJ9_1: J9.1 U3.B25(HDMI_TX1_SCL_M2/SPI2_MISO_M0/GPIO1_A4_D)
NetJ9_2: J9.2 U3.C24(HDMI_TX1_HPD_M0/SPI2_CLK_M0/GPIO1_A6_D)
NetJ9_3: J9.3 U3.A27(HDMI_TX1_SDA_M2/I2C4_SCL_M3/UART6_CTSN_M1/PWM1_M2/SPI4_CS0_M2/GPIO1_A3_D)
NetJ9_4: J9.4 U3.E27(MIPI_CAMERA2_CLK_M0/SPDIF1_TX_M0/PCIE30X2_PERSTN_M3/HDMI_RX_CEC_M2/SATA2_ACT_LED_M1/I2C5_SDA_M3/UART1_RX_M1/PWM13_M2/GPIO1_B7_U)
NetJ9_5: J9.5 U3.F24(MIPI_CAMERA3_CLK_M0/HDMI_RX_SCL_M2/I2C8_SCL_M2/UART1_RTSN_M1/PWM14_M2/GPIO1_D6_U)
NetJ9_6: J9.6 U3.F25(MIPI_CAMERA4_CLK_M0/PCIE30X2_CLKREQN_M3/HDMI_RX_SDA_M2/I2C8_SDA_M2/UART1_CTSN_M1/PWM15_IR_M3/GPIO1_D7_U)
NetJ9_7: J9.7 U3.E24(PDM1_CLK0_M1/PCIE30X1_0_PERSTN_M2/UART7_RX_M2/SPI0_CS0_M2/GPIO1_B4_U)
NetJ9_8: J9.8 U3.D27(PDM1_CLK1_M1/PCIE30X1_0_WAKEN_M2/SATA0_ACT_LED_M1/UART4_TX_M2/SPI0_CLK_M2/GPIO1_B3_D)
NetJ9_9: J9.9 U3.C25(PDM1_SDI0_M1/PCIE30X1_1_PERSTN_M2/PWM3_IR_M3/SPI2_CS0_M0/GPIO1_A7_U)
NetJ9_10: J9.10 U3.C27(PDM1_SDI1_M1/PCIE30X4_CLKREQN_M3/SPI2_CS1_M0/GPIO1_B0_U)
NetJ9_11: J9.11 U3.D25(PDM1_SDI2_M1/PCIE30X4_WAKEN_M3/SPI0_MISO_M2/GPIO1_B1_D)
NetJ9_12: J9.12 U3.D26(PDM1_SDI3_M1/PCIE30X4_PERSTN_M3/UART4_RX_M2/SPI0_MOSI_M2/GPIO1_B2_D)
NetJ10_1: J10.1 U3.AH26(CIF_D8/FSPI_CS0N_M2/PCIE30X4_CLKREQN_M2/HDMI_TX1_CEC_M2/CAN2_RX_M0/UART5_TX_M1/SPI3_CS0_M3/GPIO3_C4_U)
NetJ10_2: J10.2 U3.AH25(CIF_D9/FSPI_CS1N_M2/PCIE30X4_WAKEN_M2/HDMI_TX1_SDA_M1/CAN2_TX_M0/UART5_RX_M1/SPI3_CS1_M3/GPIO3_C5_U)
NetJ10_3: J10.3 U3.AG26(CIF_D10/PCIE30X4_PERSTN_M2/HDMI_TX1_SCL_M1/SPI3_MISO_M3/GPIO3_C6_U)
NetJ10_4: J10.4 U3.AJ24(CIF_D11/PCIE20X1_2_CLKREQN_M0/HDMI_TX0_SCL_M2/I2C5_SCL_M0/SPI3_MOSI_M3/GPIO3_C7_U)
NetJ10_5: J10.5 U3.AH24(CIF_D12/PCIE20X1_2_WAKEN_M0/HDMI_TX0_SDA_M2/I2C5_SDA_M0/UART4_RX_M1/PWM8_M2/SPI3_CLK_M3/GPIO3_D0_U)
NetJ10_6: J10.6 U3.AG23(CIF_D13/PCIE20X1_2_PERSTN_M0/HDMI_RX_CEC_M1/UART4_TX_M1/PWM9_M2/SPI0_MISO_M3/GPIO3_D1_D)
NetR3_2: R3.2 U3.T30(PMIC_SLEEP5/GPIO0_C3_D)
NetR23_2: R23.2 R26.2 U3.T34(XOUT_24M)
NetR24_1: R24.1 U3.N31(SPI2_CLK_M2/SDMMC_PWREN/PMU_DEBUG/GPIO0_A5_D)
NetR25_1: R25.1 U3.N30(SPI2_MOSI_M2/I2C0_SDA_M0/GPIO0_A6_Z)
NetR272_1: R272.1 U54.5(OE)
NetR305_1: R305.1 U3.AL26(CIF_CLKOUT/BT1120_D10/I2S1_SDO3_M0/PCIE30X4_CLKREQN_M1/DP0_HPDIN_M0/SPDIF0_TX_M1/UART9_TX_M1/PWM11_IR_M1/GPIO4_B4_U)
NetR306_1: R306.1 U3.AJ26(BT1120_D11/PCIE30X4_WAKEN_M1/HDMI_RX_CEC_M0/SATA1_ACT_LED_M0/UART9_RX_M1/PWM12_M1/SPI3_MISO_M1/GPIO4_B5_D)
NetTP6_1: TP6.1(TP) U3.Y29(GMAC1_PPSTRIG/I2C3_SDA_M1/UART7_TX_M1/SPI1_MISO_M1/GPIO3_C0_D)
NetTP7_1: TP7.1(TP) U3.Y27(GMAC1_PPSCLK/PCIE30X2_BUTTON_RSTN/UART7_RX_M1/SPI1_CLK_M1/GPIO3_C1_D)

Not connected (* = marked no-connect by the designer): IC2 3(A2) 4(A3) 5(A4) 7(B4) 9(B2); J10 9 10 11 12; U3 A24(PCIE30X1_1_CLKREQN_M2/DP0_HPDIN_M2/I2C2_SDA_M4/UART6_RX_M1/SPI4_MISO_M2/GPIO1_A0_D) A25(PCIE30X1_1_WAKEN_M2/DP1_HPDIN_M2/SATA1_ACT_LED_M1/I2C2_SCL_M4/UART6_TX_M1/SPI4_MOSI_M2/GPIO1_A1_D) A26(VOP_POST_EMPTY/I2C4_SDA_M3/UART6_RTSN_M1/PWM0_M2/SPI4_CLK_M2/GPIO1_A2_D) A28(PCIE30_PORT1_REF_CLKP) A30(PCIE30_PORT1_TX0N) A32(PCIE30_PORT1_RX0N) A33(PCIE30_PORT1_RESREF) AA25(MIPI_CSI1_AVCC0V75) AA26(MIPI_CSI1_AVCC1V8) AA27(HDMI_TX0_HPD_M1/PCIE30X2_PERSTN_M2/HDMI_RX_HPDOUT_M1/MCU_JTAG_TCK_M1/UART9_RX_M2/SPI0_CS0_M3/GPIO3_D4_D) AB25(MIPI_CSI0_AVCC0V75) AB26(MIPI_CSI0_AVCC1V8) AB28(PCIE30X4_BUTTON_RSTN/DP1_HPDIN_M0/MCU_JTAG_TMS_M1/UART9_TX_M2/PWM11_IR_M3/SPI0_CS1_M3/GPIO3_D5_D) AB30(GMAC0_PPSTRIG/FSPI_CS1N_M1/HDMI_TX1_SCL_M0/I2C4_SCL_M1/UART7_TX_M0/GPIO2_B5_U) AC30(GMAC0_PPSCLK/TEST_CLKOUT_M1/HDMI_TX1_CEC_M0/UART9_RX_M0/SPI1_CS1_M0/GPIO2_C4_D) AD1(SDMMC_D1/PDM1_SDI2_M0/JTAG_TMS_M1/I2C3_SDA_M4/UART2_RX_M1/PWM9_M1/GPIO4_D1_U) AD2(SDMMC_D0/PDM1_SDI3_M0/JTAG_TCK_M1/I2C3_SCL_M4/UART2_TX_M1/PWM8_M1/GPIO4_D0_U) AD4(NC) AD30(ETH0_REFCLKO_25M/I2S2_SDI_M0/I2C6_SCL_M2/SPI1_CS0_M0/GPIO2_C3_D) AE1(SDMMC_CLK/PDM1_CLK0_M0/TEST_CLKOUT_M0/MCU_JTAG_TMS_M0/CAN0_RX_M1/UART5_TX_M0/GPIO4_D5_D) AE2(SDMMC_CMD/PDM1_CLK1_M0/MCU_JTAG_TCK_M0/CAN0_TX_M1/UART5_RX_M0/PWM7_IR_M1/GPIO4_D4_U) AE28(GMAC1_TXER/I2S2_SDI_M1/UART2_RX_M2/PWM3_IR_M1/GPIO3_B2_D) AE30(CLK32K_OUT1/GPIO2_C5_D) AF1(SDMMC_D3/PDM1_SDI0_M0/JTAG_TMS_M0/I2C8_SDA_M0/UART5_RTSN_M0/PWM10_M1/GPIO4_D3_U) AF2(SDMMC_D2/PDM1_SDI1_M0/JTAG_TCK_M0/I2C8_SCL_M0/UART5_CTSN_M0/GPIO4_D2_U) AF18(TSADC_TEST_OUT_TS) AF19(MIPI_D/C_PHY1_VREG) AF20(MIPI_D/C_PHY0_VREG) AF33(GMAC0_TXER/I2C0_SDA_M1/UART7_CTSN_M0/PWM7_IR_M3/SPI3_CLK_M0/GPIO4_C6_D) AG19(MIPI_D/C_PHY1_VDD) AG20(MIPI_D/C_PHY0_VDD) AG24(CIF_D15/PCIE30X2_WAKEN_M2/HDMI_RX_SDA_M1/I2C7_SDA_M2/UART9_CTSN_M2/PWM10_M2/SPI0_CLK_M3/GPIO3_D3_D) AG25(CIF_D14/PCIE30X2_CLKREQN_M2/HDMI_RX_SCL_M1/I2C7_SCL_M2/UART9_RTSN_M2/SPI0_MOSI_M3/GPIO3_D2_D) AG31(MIPI_CSI1_D0P) AG32(MIPI_CSI1_D0N) AG33(MIPI_CSI0_D0P) AG34(MIPI_CSI0_D0N) AH19(MIPI_D/C_PHY1_VDD_1V2) AH20(MIPI_D/C_PHY0_VDD_1V2) AH27(ETH1_REFCLKO_25M/MIPI_CAMERA1_CLK_M1/I2C4_SCL_M0/GPIO3_A6_D) AH31(MIPI_CSI1_D1P) AH32(MIPI_CSI1_D1N) AH33(MIPI_CSI0_D1P) AH34(MIPI_CSI0_D1N) AJ19(MIPI_D/C_PHY1_VDD_1V8) AJ20(MIPI_D/C_PHY0_VDD_1V8) AJ27(BT1120_D12/PCIE30X4_PERSTN_M1/HDMI_RX_HPDOUT_M0/SATA0_ACT_LED_M0/I2C5_SCL_M1/PWM13_M1/SPI3_MOSI_M1/GPIO4_B6_D) AJ31(MIPI_CSI1_CLK0P) AJ32(MIPI_CSI1_CLK0N) AJ33(MIPI_CSI0_CLK0P) AJ34(MIPI_CSI0_CLK0N) AK15(SARADC_IN5) AK16(SARADC_IN2) AK17(SARADC_IN7) AK18(MIPI_DPHY1_RX_D0P/MIPI_CPHY1_RX_TRIO0_B) AK19(MIPI_DPHY1_RX_D1P/MIPI_CPHY1_RX_TRIO1_A) AK20(MIPI_DPHY1_RX_CLKP/MIPI_CPHY1_RX_TRIO1_C) AK21(MIPI_DPHY1_RX_D2P/MIPI_CPHY1_RX_TRIO2_B) AK22(MIPI_DPHY1_RX_D3P/NO_USE) AK31(MIPI_CSI1_D2P) AK32(MIPI_CSI1_D2N) AK33(MIPI_CSI0_D2P) AK34(MIPI_CSI0_D2N) AL17(SARADC_IN6) AL18(MIPI_DPHY1_RX_D0N/MIPI_CPHY1_RX_TRIO0_A) AL19(MIPI_DPHY1_RX_D1N/MIPI_CPHY1_RX_TRIO0_C) AL20(MIPI_DPHY1_RX_CLKN/MIPI_CPHY1_RX_TRIO1_B) AL21(MIPI_DPHY1_RX_D2N/MIPI_CPHY1_RX_TRIO2_A) AL22(MIPI_DPHY1_RX_D3N/MIPI_CPHY1_RX_TRIO2_C) AL24(MIPI_CAMERA0_CLK_M0/SPDIF1_TX_M1/I2S1_SDO0_M0/PCIE30X1_0_BUTTON_RSTN/SATA2_ACT_LED_M0/I2C6_SCL_M3/UART8_RX_M0/SPI0_CS1_M1/GPIO4_B1_U) AL28(CIF_D4/BT1120_D4/PCIE30X1_0_WAKEN_M1/I2C3_SCL_M2/UART0_RX_M2/SPI2_MISO_M1/GPIO4_A4_D) AL29(CIF_D3/BT1120_D3/PCIE30X1_0_CLKREQN_M1/UART0_TX_M2/GPIO4_A3_D) AL31(MIPI_CSI1_D3P) AL32(MIPI_CSI1_D3N) AL33(MIPI_CSI0_D3P) AL34(MIPI_CSI0_D3N) AM17(SARADC_IN4) AM25(CIF_VSYNC/BT1120_D9/I2S1_SDO2_M0/PCIE20X1_2_BUTTON_RSTN/I2C7_SDA_M3/UART8_CTSN_M0/PWM15_IR_M1/CAN1_TX_M1/GPIO4_B3_U) AM27(CIF_D7/BT1120_D7/I2S1_SDI2_M0/PCIE30X2_WAKEN_M1/I2C5_SDA_M2/SPI2_CS0_M1/GPIO4_A7_D) AM31(MIPI_CSI1_CLK1P) AM32(MIPI_CSI1_CLK1N) AM33(MIPI_CSI0_CLK1P) AM34(MIPI_CSI0_CLK1N) AN17(SARADC_IN3) AN18(MIPI_DPHY1_TX_D0P/MIPI_CPHY1_TX_TRIO0_B) AN19(MIPI_DPHY1_TX_D1P/MIPI_CPHY1_TX_TRIO1_A) AN20(MIPI_DPHY1_TX_CLKP/MIPI_CPHY1_TX_TRIO1_C) AN21(MIPI_DPHY1_TX_D2P/MIPI_CPHY1_TX_TRIO2_B) AN22(MIPI_DPHY1_TX_D3P/NO_USE) AN24(MIPI_DPHY0_TX_D0P/MIPI_CPHY0_TX_TRIO0_B) AN25(MIPI_DPHY0_TX_D1P/MIPI_CPHY0_TX_TRIO1_A) AN26(MIPI_DPHY0_TX_CLKP/MIPI_CPHY0_TX_TRIO1_C) AN27(MIPI_DPHY0_TX_D2P/MIPI_CPHY0_TX_TRIO2_B) AN28(MIPI_DPHY0_TX_D3P/NO_USE) AN29(MIPI_DPHY0_RX_D0P/MIPI_CPHY0_RX_TRIO0_B) AN30(MIPI_DPHY0_RX_D1P/MIPI_CPHY0_RX_TRIO1_A) AN32(MIPI_DPHY0_RX_CLKP/MIPI_CPHY0_RX_TRIO1_C) AN33(MIPI_DPHY0_RX_D2P/MIPI_CPHY0_RX_TRIO2_B) AN34(MIPI_DPHY0_RX_D3P/NO_USE) AP18(MIPI_DPHY1_TX_D0N/MIPI_CPHY1_TX_TRIO0_A) AP19(MIPI_DPHY1_TX_D1N/MIPI_CPHY1_TX_TRIO0_C) AP20(MIPI_DPHY1_TX_CLKN/MIPI_CPHY1_TX_TRIO1_B) AP21(MIPI_DPHY1_TX_D2N/MIPI_CPHY1_TX_TRIO2_A) AP22(MIPI_DPHY1_TX_D3N/MIPI_CPHY1_TX_TRIO2_C) AP24(MIPI_DPHY0_TX_D0N/MIPI_CPHY0_TX_TRIO0_A) AP25(MIPI_DPHY0_TX_D1N/MIPI_CPHY0_TX_TRIO0_C) AP26(MIPI_DPHY0_TX_CLKN/MIPI_CPHY0_TX_TRIO1_B) AP27(MIPI_DPHY0_TX_D2N/MIPI_CPHY0_TX_TRIO2_A) AP28(MIPI_DPHY0_TX_D3N/MIPI_CPHY0_TX_TRIO2_C) AP29(MIPI_DPHY0_RX_D0N/MIPI_CPHY0_RX_TRIO0_A) AP30(MIPI_DPHY0_RX_D1N/MIPI_CPHY0_RX_TRIO0_C) AP31(MIPI_DPHY0_RX_CLKN/MIPI_CPHY0_RX_TRIO1_B) AP32(MIPI_DPHY0_RX_D2N/MIPI_CPHY0_RX_TRIO2_A) AP33(MIPI_DPHY0_RX_D3N/MIPI_CPHY0_RX_TRIO2_C) B28(PCIE30_PORT1_REF_CLKN) B29(PCIE30_PORT1_TX1N) B30(PCIE30_PORT1_TX0P) B31(PCIE30_PORT1_RX1N) B32(PCIE30_PORT1_RX0P) B34(PCIE30_PORT0_RESREF) C29(PCIE30_PORT1_TX1P) C31(PCIE30_PORT1_RX1P) C33(PCIE30_PORT0_TX1P) C34(PCIE30_PORT0_TX1N) D28(I2S0_SDI0/GPIO1_D4_D) D29(PDM0_CLK0_M0/I2C4_SDA_M4/PWM15_IR_M2/GPIO1_C6_D) D30(I2S0_LRCK/I2C2_SCL_M3/UART4_RTSN/GPIO1_C5_D) D32(PCIE30_PORT0_TX0P) D33(PCIE30_PORT0_TX0N) E25(PCIE30X1_0_CLKREQN_M2/UART7_TX_M2/SPI0_CS1_M2/GPIO1_B5_U) E26(MIPI_CAMERA1_CLK_M0/SPDIF0_TX_M0/PCIE30X2_WAKEN_M3/HDMI_RX_HPDOUT_M2/I2C5_SCL_M3/UART1_TX_M1/GPIO1_B6_U) E28(I2S0_SDI1/PDM0_SDI3_M0/I2C1_SDA_M4/UART4_RX_M0/PWM1_M1/SPI1_CS0_M2/GPIO1_D3_D) E29(I2S0_SDO0/I2C4_SCL_M4/UART4_CTSN/GPIO1_C7_D) E30(PDM0_CLK1_M0/I2C2_SDA_M3/PWM11_IR_M2/SPI4_CS1_M0/GPIO1_C4_D) E31(I2S0_SCLK/I2C6_SCL_M1/UART3_CTSN/PWM7_IR_M2/SPI4_CS0_M0/GPIO1_C3_D) E33(PCIE30_PORT0_REF_CLKP) E34(PCIE30_PORT0_REF_CLKN) F26(I2S0_SDO1/I2C7_SCL_M0/UART6_TX_M2/SPI1_MISO_M2/GPIO1_D0_D) F27(I2S0_SDO2/I2S0_SDI3/PDM0_SDI1_M0/I2C7_SDA_M0/UART6_RX_M2/SPI1_MOSI_M2/GPIO1_D1_D) F28(I2S0_SDO3/I2S0_SDI2/PDM0_SDI2_M0/I2C1_SCL_M4/UART4_TX_M0/PWM0_M1/SPI1_CLK_M2/GPIO1_D2_D) F30(I2S0_MCLK/I2C6_SDA_M1/UART3_RTSN/PWM3_IR_M2/SPI4_CLK_M0/GPIO1_C2_D) F32(PCIE30_PORT0_RX1P) F33(PCIE30_PORT0_RX1N) G20(VCCIO1_1V8) G23(PCIE30_PORT0_AVDD1V8) G24(PCIE30_PORT0_AVDD0V75) G26(PDM0_SDI0_M0/SPI1_CS1_M2/GPIO1_D5_D) G27(I2C3_SCL_M0/UART3_TX_M0/SPI4_MOSI_M0/GPIO1_C1_Z) G29(I2C3_SDA_M0/UART3_RX_M0/SPI4_MISO_M0/GPIO1_C0_Z) G30(PCIE20_2_REFCLKN) G31(PCIE20_2_REFCLKP) G33(PCIE30_PORT0_RX0P) G34(PCIE30_PORT0_RX0N) H23(PCIE30_PORT1_AVDD1V8) H24(PCIE30_PORT1_AVDD0V75) H29(PCIE20_2_TXN/SATA30_2_TXN/USB30_2_SSTXN) H30(PCIE20_2_TXP/SATA30_2_TXP/USB30_2_SSTXP) H32(PCIE20_1_REFCLKP) H33(PCIE20_1_REFCLKN) J30(PCIE20_2_RXN/SATA30_2_RXN/USB30_2_SSRXN) J31(PCIE20_2_RXP/SATA30_2_RXP/USB30_2_SSRXP) J33(PCIE20_1_RXP/SATA30_1_RXP) J34(PCIE20_1_RXN/SATA30_1_RXN) K27(PCIE20_SATA30_USB30_2_AVDD_1V8) K28(PCIE20_SATA30_USB30_2_AVDD_0V85) K29(CLK32K_IN/CLK32K_OUT0/GPIO0_B2__U) K33(PCIE20_1_TXP/SATA30_1_TXP) K34(PCIE20_1_TXN/SATA30_1_TXN) L27(PCIE20_SATA30_1_AVDD_1V8) L28(PCIE20_SATA30_1_AVDD_0V85) L30(SPI2_CS1_M2/I2C1_SCL_M1/UART0_RX_M1/GPIO0_B0_Z) L32(PCIE20_0_REFCLKP) L33(PCIE20_0_REFCLKN) M27(PCIE20_SATA30_0_AVDD_1V8) M28(PCIE20_SATA30_0_AVDD_0V85) M33(PCIE20_0_TXN/SATA30_0_TXN) M34(PCIE20_0_TXP/SATA30_0_TXP) N33(PCIE20_0_RXP/SATA30_0_RXP) N34(PCIE20_0_RXN/SATA30_0_RXN) P30(I2S1_SDI0_M1/GPU_AVS/UART0_TX_M0/I2C4_SCL_M2/DP1_HPDIN_M1/PWM4_M0/PCIE30X1_0_PERSTN_M0/GPIO0_C5_U) P33(REFCLK_OUT/GPIO0_A0_D) R30(PDM0_CLK1_M1/PWM2_M0/UART0_RX_M0/I2C4_SDA_M2/DP0_HPDIN_M1/PCIE30X1_0_WAKEN_M0/GPIO0_C4_D) T28(I2S1_LRCK_M1/PWM0_M0/I2C2_SCL_M0/CAN0_TX_M0/SPI0_CS1_M0/PCIE30X1_1_PERSTN_M0/GPIO0_B7_D) T29(I2S1_SDI1_M1/NPU_AVS/UART0_RTSN/PWM5_M1/SPI0_CLK_M0/PCIE30X4_CLKREQN_M0/SATA_CP_POD/GPIO0_C6_U) T31(PDM0_CLK0_M1/PWM1_M0/I2C2_SDA_M0/CAN0_RX_M0/SPI0_MOSI_M0/PCIE30X1_0_CLKREQN_M0/GPIO0_C0_D)

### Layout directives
net class DP_50Ohms: (no net found under the mark)
net class RK_50OHM: (no net found under the mark), VCC_1V8_S0

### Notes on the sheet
- UART9_TX
- UART9_RX
- (near U3) DON'T NEED IN CURRENT VERSION

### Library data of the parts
C5 C15-C17 C23 C30 C32 C34 C35 C203 C204 C612 C632 = CMP-2010-00672-2: Cap Ceramic 100nF 10V X5R ±10% Pad SMD 0201 +85°C T/R; MN: CL03A104KP3NNNC
C31 C33 = CMP-03020-024161-1: C0402 18 pF X8R 5.00% 50 V; Manufacturer: Kemet; Manufacturer Part Number: 0402CG180J500NT; Value: 18 pF; Material: Ceramic; Temperature Coefficient: 15%; Tolerance: 0.05; Voltage Rating: 50 V
C683 C684 = CMP-03020-014070-2: CAP CER 0.1UF 25V X5R 0402; Manufacturer: Kemet; Material: Ceramic; Tolerance: 0.2; Temperature Coefficient: 15%
C685 C686 = CMP-03422-000114-1: CAP CER 1UF 25V X5R 0402; Manufacturer Part Number: CC0402KRX5R8BB105; Manufacturer: YAGEO; Automotive Grade: NA; Tolerance: 0.1; Material: Ceramic; Temperature Coefficient: 30ppm/°C
IC2 = NTS0104GU12,115: Voltage Level Translator Bidirectional 1 Circuit 4 Channel 50Mbps 12-XQFN _2x1.7_; MF: NXP USA
J5 = CMP-009-00061-2
J9 J10 = CMP-17439-000220-1: XL Connector Wire to Board 12PIN; Number of Contacts: 12; Current Rating: 10A; Pitch: 5mm; Voltage Rating: 150V
R3 R130 = CMP-03211-001392-1: SMD Precision Pulse Thick Film Chip Resistor; Manufacturer Part Number: CRGP0402F100K; Manufacturer: TE; Value: 100KΩ; Power Rating: 0.125W; Tolerance: 0.01; Temperature Coefficient: ±100ppm/°C; Voltage Rating: 50V
R9 = CMP-26527-001890-1: -55℃~+155℃ 0Ω 25V 50mW Thick Film Resistor 0201 Chip Resistor - Surface Mount ROHS; Resistance: 0R; MN: RMCF0201ZT0R00
R20 = CMP-1011-00124-1: 120K 0.063W 5% 0402 (1005 Metric)  SMD; Value: 120000.00 Ohm; Case-EIA: 0402; Case-Metric: 1005
R23 = CMP-2002-08016-1: Part Number: RC0402JR-07510KL; Manufacturer: Yageo
R24-R26 R305 R306 = CMP-009-00082-2: 22R 0.063W 5% 0402 (1005 Metric)  SMD; Power: 63mW; MN: 0402WGF220JTCE
R128 R272 = CMP-2002-01682-1: Manufacturer: Vishay BCcomponents; Part Number: TNPW040210K0DEED
R253 = CMP-26527-000011-1: RES 0 OHM JUMPER 1/10W 0603; Manufacturer: Stackpole; Power Rating: 0.1W; Voltage Rating: 75V; Resistance: 0mΩ; Automotive Grade: Grade 0; Value: 0mΩ
R273 = CMP-2002-01682-1: TNPW040210K0DEED; Manufacturer: Vishay BCcomponents
R301 R304 = CMP-03412-029433-1: RES SMD 2.2K OHM 1% 1/20W 0201; Manufacturer: Yageo; Value: 2.2KΩ; Power Rating: 0.05W; Temperature Coefficient: 50 ppm/°C; Tolerance: 0.01; Voltage Rating: 25V
TP2 TP6 TP7 = CMP-00028-00002-2: 0.6mm round
U3 = RK3588: low power, high performance processor; MF: Fuzhou Rockchip Electronics Co
U54 = CMP-00370-128857311-1: Single channel fixed-direction level shifter 6-SC70 -40 to 125; Manufacturer Lifecycle Status: ACTIVE; Number of Inputs: 1; Propagation Delay: 69ns; Max Junction Temperature (Tj): 150°C; Data Rate: 200Mbps; Nominal Supply Current: 2.5µA
X1 = X322524MSB4SI

## Sheet RK3588_Power.SchDoc
size D; SheetNumber: 2; SheetTotal: 22
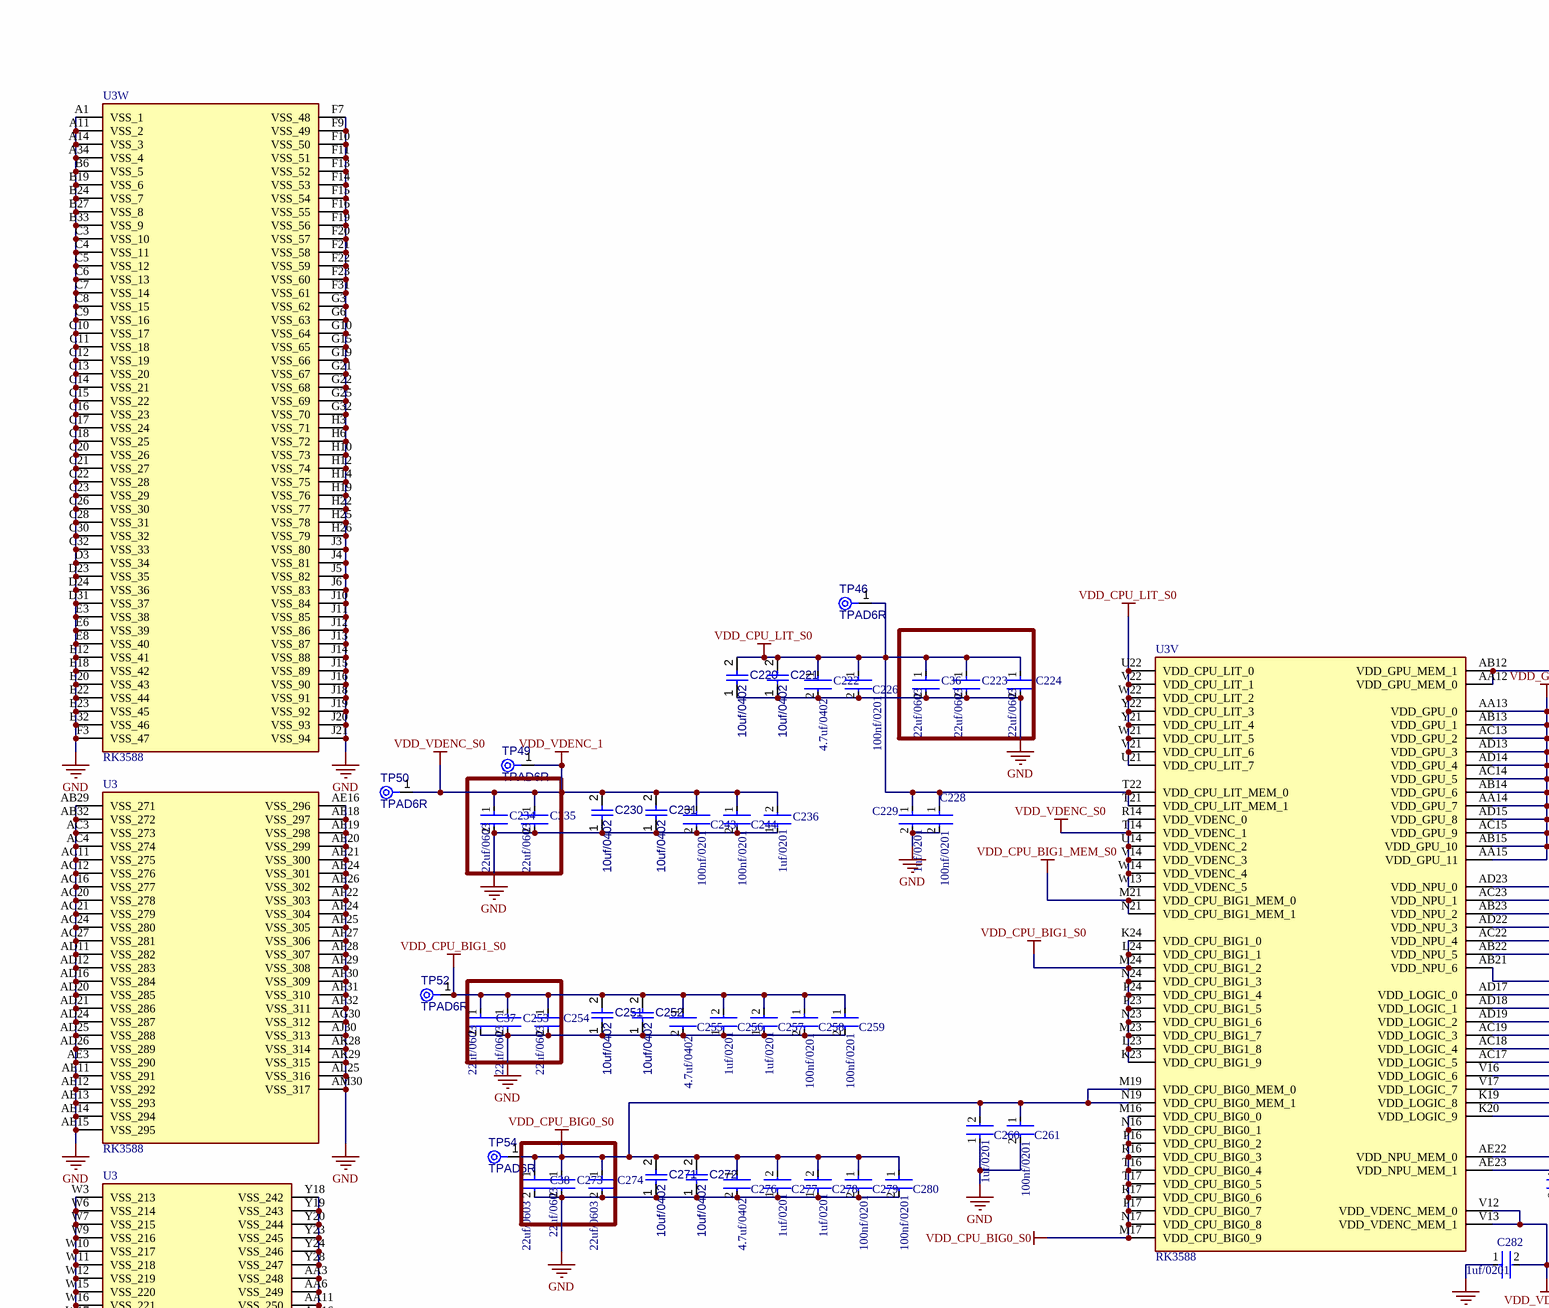
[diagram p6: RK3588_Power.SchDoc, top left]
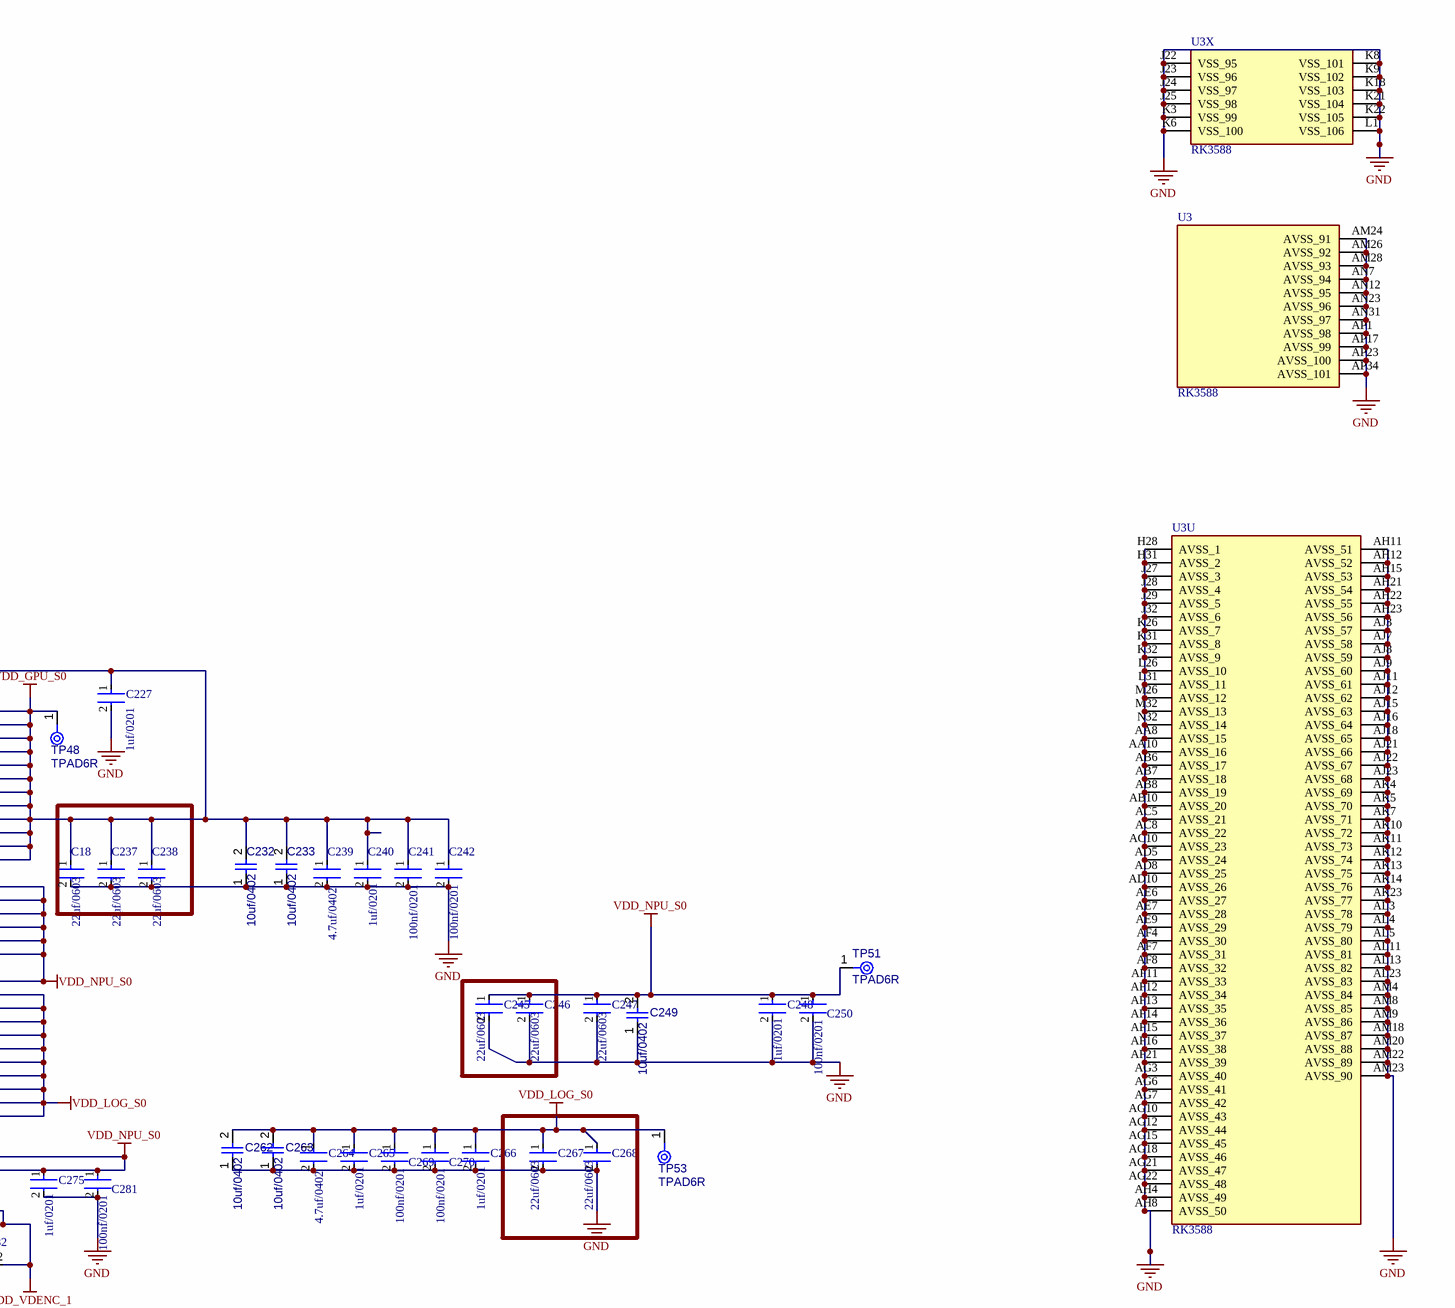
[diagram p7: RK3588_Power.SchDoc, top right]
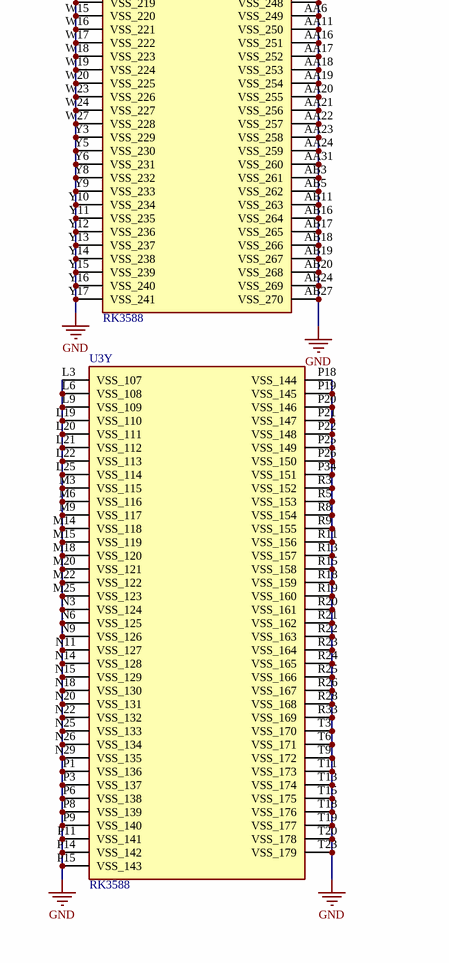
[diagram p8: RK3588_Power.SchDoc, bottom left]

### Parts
C18  22uf/0603  [FP-GRM188-0_2-MFG]
C36  22uf/0603  [FP-GRM188-0_2-MFG]
C37  22uf/0603  [FP-GRM188-0_2-MFG]
C38  22uf/0603  [FP-GRM188-0_2-MFG]
C220  10uf/0402  [CAPC0402(1005)60_L]
C221  10uf/0402  [CAPC0402(1005)60_L]
C222  4.7uf/0402  [FP-CC0402-MFG]
C223  22uf/0603  [FP-GRM188-0_2-MFG]
C224  22uf/0603  [FP-GRM188-0_2-MFG]
C226  100nf/0201  [FP-CL03-IPC_C]
C227  1uf/0201  [FP-CC0201-BA-MFG]
C228  100nf/0201  [FP-CL03-IPC_C]
C229  1uf/0201  [FP-CC0201-BA-MFG]
C230  10uf/0402  [CAPC0402(1005)60_L]
C231  10uf/0402  [CAPC0402(1005)60_L]
C232  10uf/0402  [CAPC0402(1005)60_L]
C233  10uf/0402  [CAPC0402(1005)60_L]
C234  22uf/0603  [FP-GRM188-0_2-MFG]
C235  22uf/0603  [FP-GRM188-0_2-MFG]
C236  1uf/0201  [FP-CC0201-BA-MFG]
C237  22uf/0603  [FP-GRM188-0_2-MFG]
C238  22uf/0603  [FP-GRM188-0_2-MFG]
C239  4.7uf/0402  [FP-CC0402-MFG]
C240  1uf/0201  [FP-CC0201-BA-MFG]
C241  100nf/0201  [FP-CL03-IPC_C]
C242  100nf/0201  [FP-CL03-IPC_C]
C243  100nf/0201  [FP-CL03-IPC_C]
C244  100nf/0201  [FP-CL03-IPC_C]
C245  22uf/0603  [FP-GRM188-0_2-MFG]
C246  22uf/0603  [FP-GRM188-0_2-MFG]
C247  22uf/0603  [FP-GRM188-0_2-MFG]
C248  1uf/0201  [FP-CC0201-BA-MFG]
C249  10uf/0402  [CAPC0402(1005)60_L]
C250  100nf/0201  [FP-CL03-IPC_C]
C251  10uf/0402  [CAPC0402(1005)60_L]
C252  10uf/0402  [CAPC0402(1005)60_L]
C253  22uf/0603  [FP-GRM188-0_2-MFG]
C254  22uf/0603  [FP-GRM188-0_2-MFG]
C255  4.7uf/0402  [FP-CC0402-MFG]
C256  1uf/0201  [FP-CC0201-BA-MFG]
C257  1uf/0201  [FP-CC0201-BA-MFG]
C258  100nf/0201  [FP-CL03-IPC_C]
C259  100nf/0201  [FP-CL03-IPC_C]
C260  1uf/0201  [FP-CC0201-BA-MFG]
C261  100nf/0201  [FP-CL03-IPC_C]
C262  10uf/0402  [CAPC0402(1005)60_L]
C263  10uf/0402  [CAPC0402(1005)60_L]
C264  4.7uf/0402  [FP-CC0402-MFG]
C265  1uf/0201  [FP-CC0201-BA-MFG]
C266  1uf/0201  [FP-CC0201-BA-MFG]
C267  22uf/0603  [FP-GRM188-0_2-MFG]
C268  22uf/0603  [FP-GRM188-0_2-MFG]
C269  100nf/0201  [FP-CL03-IPC_C]
C270  100nf/0201  [FP-CL03-IPC_C]
C271  10uf/0402  [CAPC0402(1005)60_L]
C272  10uf/0402  [CAPC0402(1005)60_L]
C273  22uf/0603  [FP-GRM188-0_2-MFG]
C274  22uf/0603  [FP-GRM188-0_2-MFG]
C275  1uf/0201  [FP-CC0201-BA-MFG]
C276  4.7uf/0402  [FP-CC0402-MFG]
C277  1uf/0201  [FP-CC0201-BA-MFG]
C278  1uf/0201  [FP-CC0201-BA-MFG]
C279  100nf/0201  [FP-CL03-IPC_C]
C280  100nf/0201  [FP-CL03-IPC_C]
C281  100nf/0201  [FP-CL03-IPC_C]
C282  1uf/0201  [FP-CC0201-BA-MFG]
TP46  TPAD6R  [TP06R]  (no BOM)
TP48  TPAD6R  [TP06R]  (no BOM)
TP49  TPAD6R  [TP06R]  (no BOM)
TP50  TPAD6R  [TP06R]  (no BOM)
TP51  TPAD6R  [TP06R]  (no BOM)
TP52  TPAD6R  [TP06R]  (no BOM)
TP53  TPAD6R  [TP06R]  (no BOM)
TP54  TPAD6R  [TP06R]  (no BOM)
U3  RK3588  [BGA1088C65P34X34_2300X2300X204N]  (parts U,V,W,X,Y,28,29,30 of 30)

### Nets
GND: C18.2 C36.2 C37.2 C38.2 C220.1 C221.1 C222.2 C223.2 C224.2 C226.2 C227.2 C228.2 C229.2 C230.1 C231.1 C232.1 C233.1 C234.2 C235.2 C236.1 C237.2 C238.2 C239.2 C240.2 C241.2 C242.2 C243.2 C244.2 C245.2 C246.2 C247.2 C248.2 C249.1 C250.2 C251.1 C252.1 C253.2 C254.2 C255.2 C256.1 C257.1 C258.2 C259.2 C260.1 C261.2 C262.1 C263.1 C264.2 C265.2 C266.2 C267.2 C268.2 C269.2 C270.2 C271.1 C272.1 C273.2 C274.2 C275.2 C276.2 C277.1 C278.1 C279.2 C280.2 C281.2 C282.1 U3.A1(VSS_1) U3.A11(VSS_2) U3.A14(VSS_3) U3.A34(VSS_4) U3.AA3(VSS_248) U3.AA6(VSS_249) U3.AA8(AVSS_15) U3.AA10(AVSS_16) U3.AA11(VSS_250) U3.AA16(VSS_251) U3.AA17(VSS_252) U3.AA18(VSS_253) U3.AA19(VSS_254) U3.AA20(VSS_255) U3.AA21(VSS_256) U3.AA22(VSS_257) U3.AA23(VSS_258) U3.AA24(VSS_259) U3.AA31(VSS_260) U3.AB3(VSS_261) U3.AB5(VSS_262) U3.AB6(AVSS_17) U3.AB7(AVSS_18) U3.AB8(AVSS_19) U3.AB10(AVSS_20) U3.AB11(VSS_263) U3.AB16(VSS_264) U3.AB17(VSS_265) U3.AB18(VSS_266) U3.AB19(VSS_267) U3.AB20(VSS_268) U3.AB24(VSS_269) U3.AB27(VSS_270) U3.AB29(VSS_271) U3.AB32(VSS_272) U3.AC3(VSS_273) U3.AC4(VSS_274) U3.AC5(AVSS_21) U3.AC8(AVSS_22) U3.AC10(AVSS_23) U3.AC11(VSS_275) U3.AC12(VSS_276) U3.AC16(VSS_277) U3.AC20(VSS_278) U3.AC21(VSS_279) U3.AC24(VSS_280) U3.AC27(VSS_281) U3.AD5(AVSS_24) U3.AD8(AVSS_25) U3.AD10(AVSS_26) U3.AD11(VSS_282) U3.AD12(VSS_283) U3.AD16(VSS_284) U3.AD20(VSS_285) U3.AD21(VSS_286) U3.AD24(VSS_287) U3.AD25(VSS_288) U3.AD26(VSS_289) U3.AE3(VSS_290) U3.AE6(AVSS_27) U3.AE7(AVSS_28) U3.AE9(AVSS_29) U3.AE11(VSS_291) U3.AE12(VSS_292) U3.AE13(VSS_293) U3.AE14(VSS_294) U3.AE15(VSS_295) U3.AE16(VSS_296) U3.AE18(VSS_297) U3.AE19(VSS_298) U3.AE20(VSS_299) U3.AE21(VSS_300) U3.AE24(VSS_301) U3.AE26(VSS_302) U3.AF4(AVSS_30) U3.AF7(AVSS_31) U3.AF8(AVSS_32) U3.AF11(AVSS_33) U3.AF12(AVSS_34) U3.AF13(AVSS_35) U3.AF14(AVSS_36) U3.AF15(AVSS_37) U3.AF16(AVSS_38) U3.AF21(AVSS_39) U3.AF22(VSS_303) U3.AF24(VSS_304) U3.AF25(VSS_305) U3.AF27(VSS_306) U3.AF28(VSS_307) U3.AF29(VSS_308) U3.AF30(VSS_309) U3.AF31(VSS_310) U3.AF32(VSS_311) U3.AG3(AVSS_40) U3.AG6(AVSS_41) U3.AG7(AVSS_42) U3.AG10(AVSS_43) U3.AG12(AVSS_44) U3.AG15(AVSS_45) U3.AG18(AVSS_46) U3.AG21(AVSS_47) U3.AG22(AVSS_48) U3.AG30(VSS_312) U3.AH4(AVSS_49) U3.AH8(AVSS_50) U3.AH11(AVSS_51) U3.AH12(AVSS_52) U3.AH15(AVSS_53) U3.AH21(AVSS_54) U3.AH22(AVSS_55) U3.AH23(AVSS_56) U3.AJ3(AVSS_57) U3.AJ7(AVSS_58) U3.AJ8(AVSS_59) U3.AJ9(AVSS_60) U3.AJ11(AVSS_61) U3.AJ12(AVSS_62) U3.AJ15(AVSS_63) U3.AJ16(AVSS_64) U3.AJ18(AVSS_65) U3.AJ21(AVSS_66) U3.AJ22(AVSS_67) U3.AJ23(AVSS_68) U3.AJ30(VSS_313) U3.AK4(AVSS_69) U3.AK5(AVSS_70) U3.AK7(AVSS_71) U3.AK10(AVSS_72) U3.AK11(AVSS_73) U3.AK12(AVSS_74) U3.AK13(AVSS_75) U3.AK14(AVSS_76) U3.AK23(AVSS_77) U3.AK28(VSS_314) U3.AK29(VSS_315) U3.AL3(AVSS_78) U3.AL4(AVSS_79) U3.AL5(AVSS_80) U3.AL11(AVSS_81) U3.AL13(AVSS_82) U3.AL23(AVSS_83) U3.AL25(VSS_316) U3.AM4(AVSS_84) U3.AM8(AVSS_85) U3.AM9(AVSS_86) U3.AM18(AVSS_87) U3.AM20(AVSS_88) U3.AM22(AVSS_89) U3.AM23(AVSS_90) U3.AM24(AVSS_91) U3.AM26(AVSS_92) U3.AM28(AVSS_93) U3.AM30(VSS_317) U3.AN7(AVSS_94) U3.AN12(AVSS_95) U3.AN23(AVSS_96) U3.AN31(AVSS_97) U3.AP1(AVSS_98) U3.AP17(AVSS_99) U3.AP23(AVSS_100) U3.AP34(AVSS_101) U3.B6(VSS_5) U3.B19(VSS_6) U3.B24(VSS_7) U3.B27(VSS_8) U3.B33(VSS_9) U3.C3(VSS_10) U3.C4(VSS_11) U3.C5(VSS_12) U3.C6(VSS_13) U3.C7(VSS_14) U3.C8(VSS_15) U3.C9(VSS_16) U3.C10(VSS_17) U3.C11(VSS_18) U3.C12(VSS_19) U3.C13(VSS_20) U3.C14(VSS_21) U3.C15(VSS_22) U3.C16(VSS_23) U3.C17(VSS_24) U3.C18(VSS_25) U3.C20(VSS_26) U3.C21(VSS_27) U3.C22(VSS_28) U3.C23(VSS_29) U3.C26(VSS_30) U3.C28(VSS_31) U3.C30(VSS_32) U3.C32(VSS_33) U3.D3(VSS_34) U3.D23(VSS_35) U3.D24(VSS_36) U3.D31(VSS_37) U3.E3(VSS_38) U3.E6(VSS_39) U3.E8(VSS_40) U3.E12(VSS_41) U3.E18(VSS_42) U3.E20(VSS_43) U3.E22(VSS_44) U3.E23(VSS_45) U3.E32(VSS_46) U3.F3(VSS_47) U3.F7(VSS_48) U3.F9(VSS_49) U3.F10(VSS_50) U3.F11(VSS_51) U3.F13(VSS_52) U3.F14(VSS_53) U3.F15(VSS_54) U3.F16(VSS_55) U3.F19(VSS_56) U3.F20(VSS_57) U3.F21(VSS_58) U3.F22(VSS_59) U3.F23(VSS_60) U3.F31(VSS_61) U3.G3(VSS_62) U3.G6(VSS_63) U3.G10(VSS_64) U3.G15(VSS_65) U3.G19(VSS_66) U3.G21(VSS_67) U3.G22(VSS_68) U3.G25(VSS_69) U3.G32(VSS_70) U3.H3(VSS_71) U3.H6(VSS_72) U3.H10(VSS_73) U3.H12(VSS_74) U3.H14(VSS_75) U3.H19(VSS_76) U3.H22(VSS_77) U3.H25(VSS_78) U3.H26(VSS_79) U3.H28(AVSS_1) U3.H31(AVSS_2) U3.J3(VSS_80) U3.J4(VSS_81) U3.J5(VSS_82) U3.J6(VSS_83) U3.J10(VSS_84) U3.J11(VSS_85) U3.J12(VSS_86) U3.J13(VSS_87) U3.J14(VSS_88) U3.J15(VSS_89) U3.J16(VSS_90) U3.J18(VSS_91) U3.J19(VSS_92) U3.J20(VSS_93) U3.J21(VSS_94) U3.J22(VSS_95) U3.J23(VSS_96) U3.J24(VSS_97) U3.J25(VSS_98) U3.J27(AVSS_3) U3.J28(AVSS_4) U3.J29(AVSS_5) U3.J32(AVSS_6) U3.K3(VSS_99) U3.K6(VSS_100) U3.K8(VSS_101) U3.K9(VSS_102) U3.K18(VSS_103) U3.K21(VSS_104) U3.K22(VSS_105) U3.K26(AVSS_7) U3.K31(AVSS_8) U3.K32(AVSS_9) U3.L1(VSS_106) U3.L3(VSS_107) U3.L6(VSS_108) U3.L9(VSS_109) U3.L19(VSS_110) U3.L20(VSS_111) U3.L21(VSS_112) U3.L22(VSS_113) U3.L25(VSS_114) U3.L26(AVSS_10) U3.L31(AVSS_11) U3.M3(VSS_115) U3.M6(VSS_116) U3.M9(VSS_117) U3.M14(VSS_118) U3.M15(VSS_119) U3.M18(VSS_120) U3.M20(VSS_121) U3.M22(VSS_122) U3.M25(VSS_123) U3.M26(AVSS_12) U3.M32(AVSS_13) U3.N3(VSS_124) U3.N6(VSS_125) U3.N9(VSS_126) U3.N11(VSS_127) U3.N14(VSS_128) U3.N15(VSS_129) U3.N18(VSS_130) U3.N20(VSS_131) U3.N22(VSS_132) U3.N25(VSS_133) U3.N26(VSS_134) U3.N29(VSS_135) U3.N32(AVSS_14) U3.P1(VSS_136) U3.P3(VSS_137) U3.P6(VSS_138) U3.P8(VSS_139) U3.P9(VSS_140) U3.P11(VSS_141) U3.P14(VSS_142) U3.P15(VSS_143) U3.P18(VSS_144) U3.P19(VSS_145) U3.P20(VSS_146) U3.P21(VSS_147) U3.P22(VSS_148) U3.P25(VSS_149) U3.P26(VSS_150) U3.P34(VSS_151) U3.R3(VSS_152) U3.R5(VSS_153) U3.R8(VSS_154) U3.R9(VSS_155) U3.R11(VSS_156) U3.R13(VSS_157) U3.R15(VSS_158) U3.R18(VSS_159) U3.R19(VSS_160) U3.R20(VSS_161) U3.R21(VSS_162) U3.R22(VSS_163) U3.R23(VSS_164) U3.R24(VSS_165) U3.R25(VSS_166) U3.R26(VSS_167) U3.R28(VSS_168) U3.R33(VSS_169) U3.T3(VSS_170) U3.T6(VSS_171) U3.T9(VSS_172) U3.T11(VSS_173) U3.T13(VSS_174) U3.T15(VSS_175) U3.T18(VSS_176) U3.T19(VSS_177) U3.T20(VSS_178) U3.T23(VSS_179) U3.W3(VSS_213) U3.W6(VSS_214) U3.W7(VSS_215) U3.W9(VSS_216) U3.W10(VSS_217) U3.W11(VSS_218) U3.W12(VSS_219) U3.W15(VSS_220) U3.W16(VSS_221) U3.W17(VSS_222) U3.W18(VSS_223) U3.W19(VSS_224) U3.W20(VSS_225) U3.W23(VSS_226) U3.W24(VSS_227) U3.W27(VSS_228) U3.Y3(VSS_229) U3.Y5(VSS_230) U3.Y6(VSS_231) U3.Y8(VSS_232) U3.Y9(VSS_233) U3.Y10(VSS_234) U3.Y11(VSS_235) U3.Y12(VSS_236) U3.Y13(VSS_237) U3.Y14(VSS_238) U3.Y15(VSS_239) U3.Y16(VSS_240) U3.Y17(VSS_241) U3.Y18(VSS_242) U3.Y19(VSS_243) U3.Y20(VSS_244) U3.Y23(VSS_245) U3.Y24(VSS_246) U3.Y28(VSS_247)
VDD_CPU_BIG0_S0: C38.1 C260.2 C261.1 C271.2 C272.2 C273.1 C274.1 C276.1 C277.2 C278.2 C279.1 C280.1 TP54.1(TP) U3.M16(VDD_CPU_BIG0_0) U3.M17(VDD_CPU_BIG0_9) U3.M19(VDD_CPU_BIG0_MEM_0) U3.N16(VDD_CPU_BIG0_1) U3.N17(VDD_CPU_BIG0_8) U3.N19(VDD_CPU_BIG0_MEM_1) U3.P16(VDD_CPU_BIG0_2) U3.P17(VDD_CPU_BIG0_7) U3.R16(VDD_CPU_BIG0_3) U3.R17(VDD_CPU_BIG0_6) U3.T16(VDD_CPU_BIG0_4) U3.T17(VDD_CPU_BIG0_5)
VDD_CPU_BIG1_MEM_S0: U3.M21(VDD_CPU_BIG1_MEM_0) U3.N21(VDD_CPU_BIG1_MEM_1)
VDD_CPU_BIG1_S0: C37.1 C251.2 C252.2 C253.1 C254.1 C255.1 C256.2 C257.2 C258.1 C259.1 TP52.1(TP) U3.K23(VDD_CPU_BIG1_9) U3.K24(VDD_CPU_BIG1_0) U3.L23(VDD_CPU_BIG1_8) U3.L24(VDD_CPU_BIG1_1) U3.M23(VDD_CPU_BIG1_7) U3.M24(VDD_CPU_BIG1_2) U3.N23(VDD_CPU_BIG1_6) U3.N24(VDD_CPU_BIG1_3) U3.P23(VDD_CPU_BIG1_5) U3.P24(VDD_CPU_BIG1_4)
VDD_CPU_LIT_S0: C36.1 C220.2 C221.2 C222.1 C223.1 C224.1 C226.1 C228.1 C229.1 TP46.1(TP) U3.T21(VDD_CPU_LIT_MEM_1) U3.T22(VDD_CPU_LIT_MEM_0) U3.U21(VDD_CPU_LIT_7) U3.U22(VDD_CPU_LIT_0) U3.V21(VDD_CPU_LIT_6) U3.V22(VDD_CPU_LIT_1) U3.W21(VDD_CPU_LIT_5) U3.W22(VDD_CPU_LIT_2) U3.Y21(VDD_CPU_LIT_4) U3.Y22(VDD_CPU_LIT_3)
VDD_GPU_S0: C18.1 C227.1 C232.2 C233.2 C237.1 C238.1 C239.1 C240.1 C241.1 C242.1 TP48.1(TP) U3.AA12(VDD_GPU_MEM_0) U3.AA13(VDD_GPU_0) U3.AA14(VDD_GPU_7) U3.AA15(VDD_GPU_11) U3.AB12(VDD_GPU_MEM_1) U3.AB13(VDD_GPU_1) U3.AB14(VDD_GPU_6) U3.AB15(VDD_GPU_10) U3.AC13(VDD_GPU_2) U3.AC14(VDD_GPU_5) U3.AC15(VDD_GPU_9) U3.AD13(VDD_GPU_3) U3.AD14(VDD_GPU_4) U3.AD15(VDD_GPU_8)
VDD_LOG_S0: C262.2 C263.2 C264.1 C265.1 C266.1 C267.1 C268.1 C269.1 C270.1 TP53.1(TP) U3.AC17(VDD_LOGIC_5) U3.AC18(VDD_LOGIC_4) U3.AC19(VDD_LOGIC_3) U3.AD17(VDD_LOGIC_0) U3.AD18(VDD_LOGIC_1) U3.AD19(VDD_LOGIC_2) U3.K19(VDD_LOGIC_8) U3.K20(VDD_LOGIC_9) U3.V16(VDD_LOGIC_6) U3.V17(VDD_LOGIC_7)
VDD_NPU_S0: C245.1 C246.1 C247.1 C248.1 C249.2 C250.1 C275.1 C281.1 TP51.1(TP) U3.AB21(VDD_NPU_6) U3.AB22(VDD_NPU_5) U3.AB23(VDD_NPU_2) U3.AC22(VDD_NPU_4) U3.AC23(VDD_NPU_1) U3.AD22(VDD_NPU_3) U3.AD23(VDD_NPU_0) U3.AE22(VDD_NPU_MEM_0) U3.AE23(VDD_NPU_MEM_1)
VDD_VDENC_S0: C230.2 C231.2 C234.1 C235.1 C236.2 C243.1 C244.1 C282.2 TP49.1(TP) TP50.1(TP) U3.R14(VDD_VDENC_0) U3.T14(VDD_VDENC_1) U3.U14(VDD_VDENC_2) U3.V12(VDD_VDENC_MEM_0) U3.V13(VDD_VDENC_MEM_1) U3.V14(VDD_VDENC_3) U3.W13(VDD_VDENC_5) U3.W14(VDD_VDENC_4)  [also labelled VDD_VDENC_1]

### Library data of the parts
C18 C36-C38 C223 C224 C234 C235 C237 C238 C245-C247 C253 C254 C267 C268 C273 C274 = CMP-06035-063649-1: 10V 22uF X5R ±20% 0603 Multilayer Ceramic Capacitors MLCC - SMD/SMT ROHS; MN: CL10A226MP8NUNE
C220 C221 C230-C233 C249 C251 C252 C262 C263 C271 C272 = CMP-001-00074-3: 10uF 6.3V X5R ±20% 0402 Multilayer Ceramic Capacitors MLCC - SMD/SMT ROHS; Value: 10µF; Tolerance: 10%; MN: GRM155R60J106ME44D
C222 C239 C255 C264 C276 = CMP-03422-000823-1: 10V 4.7uF X5R ±10% 0402 Multilayer Ceramic Capacitors MLCC - SMD/SMT ROHS; Manufacturer Part Number: CC0402KRX5R6BB475; Manufacturer: YAGEO; Automotive Grade: NA; Temperature Coefficient: 30ppm/°C; Tolerance: 0.1
C226 C228 C241-C244 C250 C258 C259 C261 C269 C270 C279-C281 = CMP-2010-00672-2: as C5 on sheet rk3588
C227 C229 C236 C240 C248 C256 C257 C260 C265 C266 C275 C277 C278 C282 = CMP-03422-000660-2: 1uF 6.3V X5R ±20% 0201 Multilayer Ceramic Capacitors MLCC - SMD/SMT ROHS; Manufacturer: Yageo; Manufacturer Part Number: CC0201MRX5R5BB105; Tolerance: 0.2; Temperature Coefficient: 15%; MN: CL03A105MQ3CSNH
TP46 TP48-TP54 = CMP-00028-00002-2: 0.6mm round
U3 = RK3588: as U3 on sheet rk3588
